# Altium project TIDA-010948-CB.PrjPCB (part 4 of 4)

## Sheet TIDA-010948-CB-Ethernet2.SchDoc
size 431 x 279 mm; Date: Not shown in title block; ApprovedBy: Not shown in title block; CheckedBy: Not shown in title block; Author: Not shown in title block; CompanyName: Not shown in title block; Engineer: Not shown in title block; Organization: Not shown in title block; Address1: Not shown in title block; Address2: Not shown in title block; Address3: Not shown in title block; Address4: Not shown in title block; DocumentNumber: 9; Revision: Use project parameter SCH_Rev; SheetNumber: 9; SheetTotal: 11; PageSetup: Record=PageOptions¦CenterHorizontal=True¦CenterVertical=True¦PrintScale=1.00¦XCorrection=1.00¦YCorrection=1.00¦PrintKind=0¦BorderSize=5000000¦LeftOffset=0¦BottomOffset=0¦Orientation=2¦PaperLength=1000¦PaperWidth=1000¦Scale=100¦PaperSource=15¦PrintQuality=600¦MediaType=1¦DitherType=10¦PaperKind=Letter¦PrintScaleMode=1
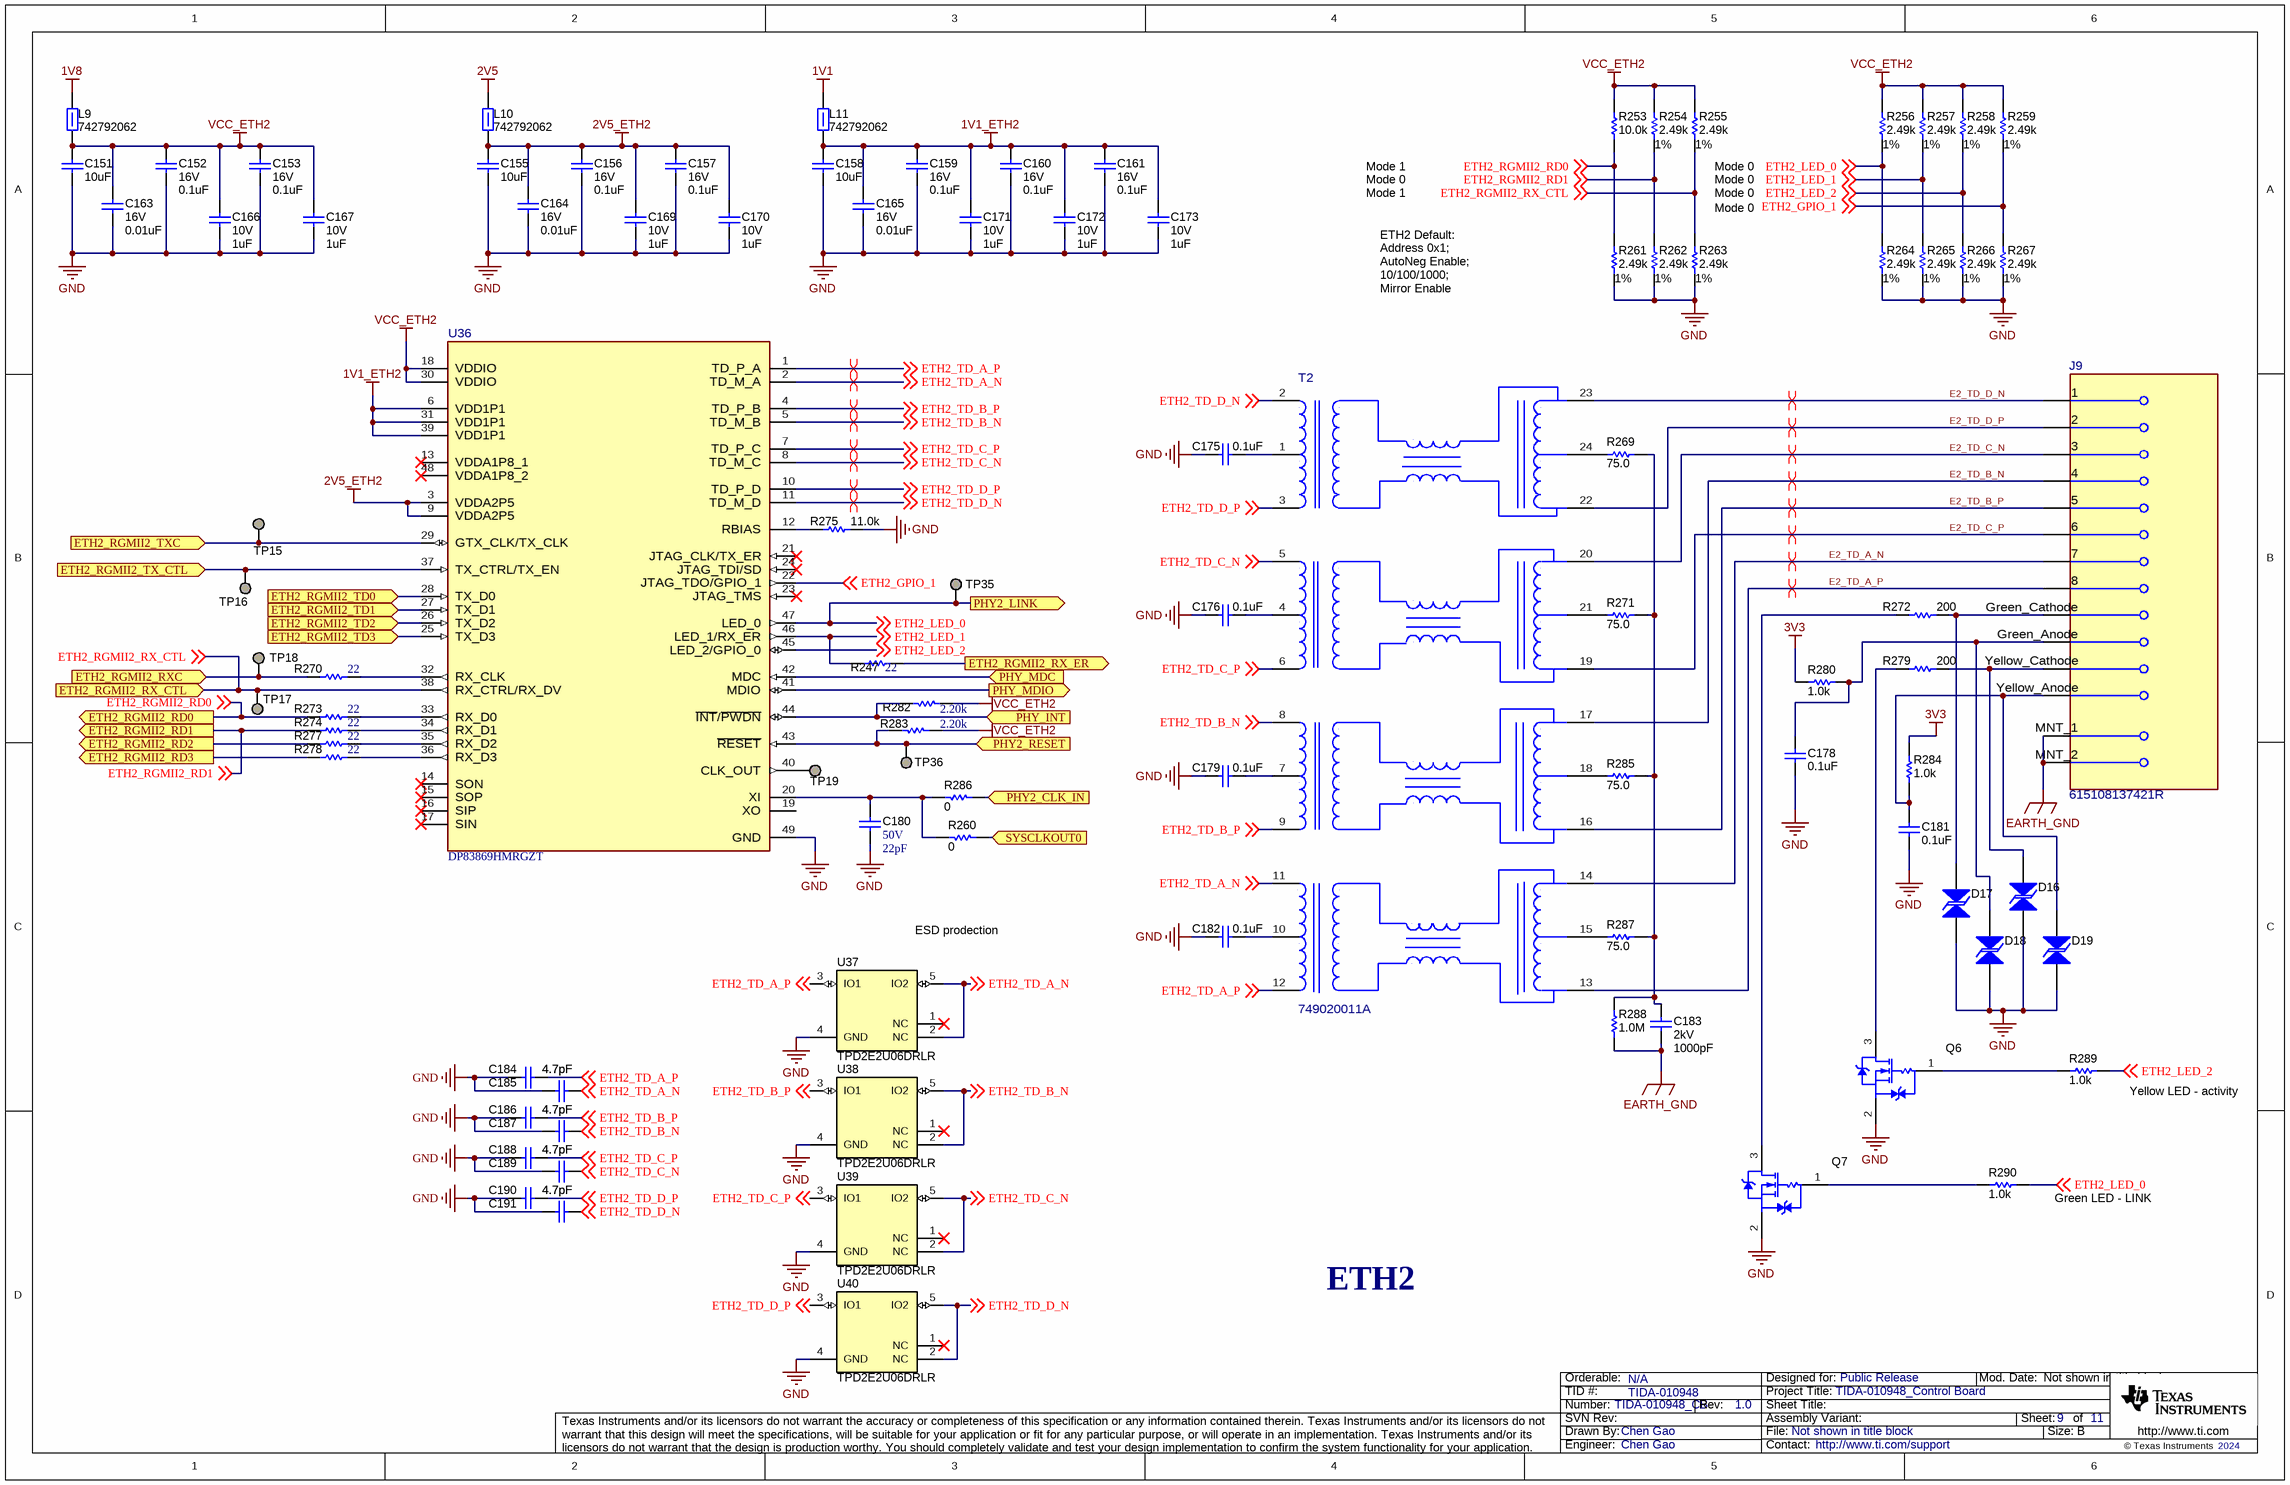
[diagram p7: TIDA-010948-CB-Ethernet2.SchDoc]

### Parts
C151  ValueDisplayed: 10uF  [1206_190]  (hidden comment: C3216X7R1V106M160AC)
C152  VDC_V: 16V  ValueDisplayed: 0.1uF  [0201_033]  (hidden comment: GRM033C71C104KE14D)
C153  VDC_V: 16V  ValueDisplayed: 0.1uF  [0201_033]  (hidden comment: GRM033C71C104KE14D)
C155  ValueDisplayed: 10uF  [1206_190]  (hidden comment: C3216X7R1V106M160AC)
C156  VDC_V: 16V  ValueDisplayed: 0.1uF  [0201_033]  (hidden comment: GRM033C71C104KE14D)
C157  VDC_V: 16V  ValueDisplayed: 0.1uF  [0201_033]  (hidden comment: GRM033C71C104KE14D)
C158  ValueDisplayed: 10uF  [1206_190]  (hidden comment: C3216X7R1V106M160AC)
C159  VDC_V: 16V  ValueDisplayed: 0.1uF  [0201_033]  (hidden comment: GRM033C71C104KE14D)
C160  VDC_V: 16V  ValueDisplayed: 0.1uF  [0201_033]  (hidden comment: GRM033C71C104KE14D)
C161  VDC_V: 16V  ValueDisplayed: 0.1uF  [0201_033]  (hidden comment: GRM033C71C104KE14D)
C163  VDC_V: 16V  ValueDisplayed: 0.01uF  [0402]  (hidden comment: 885012205031)
C164  VDC_V: 16V  ValueDisplayed: 0.01uF  [0402]  (hidden comment: 885012205031)
C165  VDC_V: 16V  ValueDisplayed: 0.01uF  [0402]  (hidden comment: 885012205031)
C166  VDC_V: 10V  ValueDisplayed: 1uF  [0201]  (hidden comment: GRM033R61A105ME15D)
C167  VDC_V: 10V  ValueDisplayed: 1uF  [0201]  (hidden comment: GRM033R61A105ME15D)
C169  VDC_V: 10V  ValueDisplayed: 1uF  [0201]  (hidden comment: GRM033R61A105ME15D)
C170  VDC_V: 10V  ValueDisplayed: 1uF  [0201]  (hidden comment: GRM033R61A105ME15D)
C171  VDC_V: 10V  ValueDisplayed: 1uF  [0201]  (hidden comment: GRM033R61A105ME15D)
C172  VDC_V: 10V  ValueDisplayed: 1uF  [0201]  (hidden comment: GRM033R61A105ME15D)
C173  VDC_V: 10V  ValueDisplayed: 1uF  [0201]  (hidden comment: GRM033R61A105ME15D)
C175  ValueDisplayed: 0.1uF  [0402]  (hidden comment: GRM155R71C104KA88D)
C176  ValueDisplayed: 0.1uF  [0402]  (hidden comment: GRM155R71C104KA88D)
C178  ValueDisplayed: 0.1uF  [0402]  (hidden comment: 885012105010)
C179  ValueDisplayed: 0.1uF  [0402]  (hidden comment: GRM155R71C104KA88D)
C180  VDC_V: 50V  ValueDisplayed: 22pF  [0402L]  (hidden comment: CGA2B2NP01H220J050BA)
C181  ValueDisplayed: 0.1uF  [0402]  (hidden comment: 885012105010)
C182  ValueDisplayed: 0.1uF  [0402]  (hidden comment: GRM155R71C104KA88D)
C183  VDC_V: 2kV  ValueDisplayed: 1000pF  [1808]  (hidden comment: GR442QR73D102KW01L)
C184  ValueDisplayed: 4.7pF  [0201L]  (hidden comment: GRM0335C1H4R7CA01D)
C185  ValueDisplayed: 4.7pF  [0201L]  (hidden comment: GRM0335C1H4R7CA01D)
C186  ValueDisplayed: 4.7pF  [0201L]  (hidden comment: GRM0335C1H4R7CA01D)
C187  ValueDisplayed: 4.7pF  [0201L]  (hidden comment: GRM0335C1H4R7CA01D)
C188  ValueDisplayed: 4.7pF  [0201L]  (hidden comment: GRM0335C1H4R7CA01D)
C189  ValueDisplayed: 4.7pF  [0201L]  (hidden comment: GRM0335C1H4R7CA01D)
C190  ValueDisplayed: 4.7pF  [0201L]  (hidden comment: GRM0335C1H4R7CA01D)
C191  ValueDisplayed: 4.7pF  [0201L]  (hidden comment: GRM0335C1H4R7CA01D)
D16  TPD1E1B04DPYR  [DPY0002A]  (value not drawn)
D17  TPD1E1B04DPYR  [DPY0002A]  (value not drawn)
D18  TPD1E1B04DPYR  [DPY0002A]  (value not drawn)
D19  TPD1E1B04DPYR  [DPY0002A]  (value not drawn)
J9  615108137421R  [FP-615108137421R_CONN_JACK_16MM4_15MM7-MFG]
L9  742792062  [0805_HV]
L10  742792062  [0805_HV]
L11  742792062  [0805_HV]
Q6  MOSFET_N_D3G1S2_PD2  [YJC0003A]  (value not drawn)
Q7  MOSFET_N_D3G1S2_PD2  [YJC0003A]  (value not drawn)
R247  ValueDisplayed: 22  [0402L]  (hidden comment: CRCW040222R0JNED)
R253  ValueDisplayed: 10.0k  [0402]  (hidden comment: CRCW040210K0FKED)
R254  Value1: 1%  ValueDisplayed: 2.49k  [0402]  (hidden comment: CRCW04022K49FKED)
R255  Value1: 1%  ValueDisplayed: 2.49k  [0402]  (hidden comment: CRCW04022K49FKED)
R256  Value1: 1%  ValueDisplayed: 2.49k  [0402]  (hidden comment: CRCW04022K49FKED)
R257  Value1: 1%  ValueDisplayed: 2.49k  [0402]  (hidden comment: CRCW04022K49FKED)
R258  Value1: 1%  ValueDisplayed: 2.49k  [0402]  (hidden comment: CRCW04022K49FKED)
R259  Value1: 1%  ValueDisplayed: 2.49k  [0402]  (hidden comment: CRCW04022K49FKED)
R260  ValueDisplayed: 0  [0402]  (hidden comment: CRCW04020000Z0ED)
R261  Value1: 1%  ValueDisplayed: 2.49k  [0402]  (hidden comment: CRCW04022K49FKED)
R262  Value1: 1%  ValueDisplayed: 2.49k  [0402]  (hidden comment: CRCW04022K49FKED)
R263  Value1: 1%  ValueDisplayed: 2.49k  [0402]  (hidden comment: CRCW04022K49FKED)
R264  Value1: 1%  ValueDisplayed: 2.49k  [0402]  (hidden comment: CRCW04022K49FKED)
R265  Value1: 1%  ValueDisplayed: 2.49k  [0402]  (hidden comment: CRCW04022K49FKED)
R266  Value1: 1%  ValueDisplayed: 2.49k  [0402]  (hidden comment: CRCW04022K49FKED)
R267  Value1: 1%  ValueDisplayed: 2.49k  [0402]  (hidden comment: CRCW04022K49FKED)
R269  ValueDisplayed: 75.0  [0805_HV]  (hidden comment: CRCW080575R0FKEA)
R270  ValueDisplayed: 22  [0402L]  (hidden comment: CRCW040222R0JNED)
R271  ValueDisplayed: 75.0  [0805_HV]  (hidden comment: CRCW080575R0FKEA)
R272  ValueDisplayed: 200  [0402]  (hidden comment: CRCW0402200RFKED)
R273  ValueDisplayed: 22  [0402L]  (hidden comment: CRCW040222R0JNED)
R274  ValueDisplayed: 22  [0402L]  (hidden comment: CRCW040222R0JNED)
R275  ValueDisplayed: 11.0k  [0402]  (hidden comment: CRCW040211K0FKED)
R277  ValueDisplayed: 22  [0402L]  (hidden comment: CRCW040222R0JNED)
R278  ValueDisplayed: 22  [0402L]  (hidden comment: CRCW040222R0JNED)
R279  ValueDisplayed: 200  [0402]  (hidden comment: CRCW0402200RFKED)
R280  ValueDisplayed: 1.0k  [0402]  (hidden comment: CRCW04021K00JNED)
R282  ValueDisplayed: 2.20k  [0402L]  (hidden comment: CRCW04022K20FKED)
R283  ValueDisplayed: 2.20k  [0402L]  (hidden comment: CRCW04022K20FKED)
R284  ValueDisplayed: 1.0k  [0402]  (hidden comment: CRCW04021K00JNED)
R285  ValueDisplayed: 75.0  [0805_HV]  (hidden comment: CRCW080575R0FKEA)
R286  ValueDisplayed: 0  [0402]  (hidden comment: CRCW04020000Z0ED)
R287  ValueDisplayed: 75.0  [0805_HV]  (hidden comment: CRCW080575R0FKEA)
R288  ValueDisplayed: 1.0M  [2010]  (hidden comment: CRCW20101M00JNEF)
R289  ValueDisplayed: 1.0k  [0402]  (hidden comment: CRCW04021K00JNED)
R290  ValueDisplayed: 1.0k  [0402]  (hidden comment: CRCW04021K00JNED)
T2  749020011A  [FP-749020011A_SMT_17MM5_14MM2-MFG]
TP15  TESTPOINT  [TP_25MIL-SMT]  (value not drawn)  (no BOM)
TP16  TESTPOINT  [TP_25MIL-SMT]  (value not drawn)  (no BOM)
TP17  TESTPOINT  [TP_25MIL-SMT]  (value not drawn)  (no BOM)
TP18  TESTPOINT  [TP_25MIL-SMT]  (value not drawn)  (no BOM)
TP19  TESTPOINT  [TP_25MIL-SMT]  (value not drawn)  (no BOM)
TP35  TESTPOINT  [TP_25MIL-SMT]  (value not drawn)  (no BOM)
TP36  TESTPOINT  [TP_25MIL-SMT]  (value not drawn)  (no BOM)
U36  DP83869HMRGZT  [RGZ0048B-MFG]
U37  TPD2E2U06DRLR  [DRL0005A]
U38  TPD2E2U06DRLR  [DRL0005A]
U39  TPD2E2U06DRLR  [DRL0005A]
U40  TPD2E2U06DRLR  [DRL0005A]

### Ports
ETH2_RGMII2_RD0 (out), ETH2_RGMII2_RD1 (out), ETH2_RGMII2_RD2 (out), ETH2_RGMII2_RD3 (out), ETH2_RGMII2_RX_CTL (in), ETH2_RGMII2_RX_ER (out), ETH2_RGMII2_RXC (in), ETH2_RGMII2_TD0 (in), ETH2_RGMII2_TD1 (in), ETH2_RGMII2_TD2 (in), ETH2_RGMII2_TD3 (in), ETH2_RGMII2_TX_CTL (in), ETH2_RGMII2_TXC (in), PHY2_CLK_IN (in), PHY2_LINK (out), PHY2_RESET (in), PHY_INT (in), PHY_MDC (in), PHY_MDIO (out), SYSCLKOUT0 (in)

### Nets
1V1: L11.2
1V1_ETH2: C158.1 C159.1 C160.1 C161.1 C165.1 C171.1 C172.1 C173.1 L11.1 U36.6(VDD1P1) U36.31(VDD1P1) U36.39(VDD1P1)
1V8: L9.2
2V5: L10.2
2V5_ETH2: C155.1 C156.1 C157.1 C164.1 C169.1 C170.1 L10.1 U36.3(VDDA2P5) U36.9(VDDA2P5)
3V3: R280.2 R284.1
EARTH_GND: C183.2 J9.13(MNT_1) J9.14(MNT_2) R288.1
GND: C151.2 C152.2 C153.2 C155.2 C156.2 C157.2 C158.2 C159.2 C160.2 C161.2 C163.2 C164.2 C165.2 C166.2 C167.2 C169.2 C170.2 C171.2 C172.2 C173.2 C175.2 C176.2 C178.1 C179.2 C180.2 C181.1 C182.2 C184.1 C185.1 C186.1 C187.1 C188.1 C189.1 C190.1 C191.1 D16.1 D17.1 D18.1 D19.1 Q6.2(S) Q7.2(S) R261.1 R262.1 R263.1 R264.1 R265.1 R266.1 R267.1 R275.2 U36.49(GND) U37.4(GND) U38.4(GND) U39.4(GND) U40.4(GND)
VCC_ETH2: C151.1 C152.1 C153.1 C163.1 C166.1 C167.1 L9.1 R253.2 R254.2 R255.2 R256.2 R257.2 R258.2 R259.2 R282.1 R283.1 U36.18(VDDIO) U36.30(VDDIO)
E2_TD_A_N: J9.7 T2.14(MX4+)
E2_TD_A_P: J9.8 T2.13(MX4-)
E2_TD_B_N: J9.4 T2.17(MX3+)
E2_TD_B_P: J9.5 T2.16(MX3-)
E2_TD_C_N: J9.3 T2.20(MX2+)
E2_TD_C_P: J9.6 T2.19(MX2-)
E2_TD_D_N: J9.1 T2.23(MX1+)
E2_TD_D_P: J9.2 T2.22(MX1-)
ETH2_GPIO_1: R259.1 R267.2 U36.22(JTAG_TDO/GPIO_1) ; off-sheet ETH2_GPIO_1
ETH2_LED_0: R256.1 R264.2 R290.1 TP35.1 U36.47(LED_0) ; off-sheet ETH2_LED_0, port PHY2_LINK
ETH2_LED_1: R247.1 R257.1 R265.2 U36.46(LED_1/RX_ER) ; off-sheet ETH2_LED_1
ETH2_LED_2: R258.1 R266.2 R289.1 U36.45(LED_2/GPIO_0) ; off-sheet ETH2_LED_2
ETH2_RGMII2_RD0: R253.1 R261.2 R273.1 ; off-sheet ETH2_RGMII2_RD0, port ETH2_RGMII2_RD0
ETH2_RGMII2_RD1: R254.1 R262.2 R274.1 ; off-sheet ETH2_RGMII2_RD1, port ETH2_RGMII2_RD1
ETH2_RGMII2_RD2: R277.1 ; port ETH2_RGMII2_RD2
ETH2_RGMII2_RD3: R278.1 ; port ETH2_RGMII2_RD3
ETH2_RGMII2_RX_CTL: R255.1 R263.2 TP17.1 U36.38(RX_CTRL/RX_DV) ; off-sheet ETH2_RGMII2_RX_CTL, port ETH2_RGMII2_RX_CTL
ETH2_RGMII2_RX_ER: R247.2 ; port ETH2_RGMII2_RX_ER
ETH2_RGMII2_RXC: R270.1 TP18.1 ; port ETH2_RGMII2_RXC
ETH2_RGMII2_TD0: U36.28(TX_D0) ; port ETH2_RGMII2_TD0
ETH2_RGMII2_TD1: U36.27(TX_D1) ; port ETH2_RGMII2_TD1
ETH2_RGMII2_TD2: U36.26(TX_D2) ; port ETH2_RGMII2_TD2
ETH2_RGMII2_TD3: U36.25(TX_D3) ; port ETH2_RGMII2_TD3
ETH2_RGMII2_TX_CTL: TP16.1 U36.37(TX_CTRL/TX_EN) ; port ETH2_RGMII2_TX_CTL
ETH2_RGMII2_TXC: TP15.1 U36.29(GTX_CLK/TX_CLK) ; port ETH2_RGMII2_TXC
ETH2_TD_A_N: C185.2 T2.11(TD4+) U36.2(TD_M_A) U37.2(NC) U37.5(IO2) ; off-sheet ETH2_TD_A_N
ETH2_TD_A_P: C184.2 T2.12(TD4-) U36.1(TD_P_A) U37.3(IO1) ; off-sheet ETH2_TD_A_P
ETH2_TD_B_N: C187.2 T2.8(TD3+) U36.5(TD_M_B) U38.2(NC) U38.5(IO2) ; off-sheet ETH2_TD_B_N
ETH2_TD_B_P: C186.2 T2.9(TD3-) U36.4(TD_P_B) U38.3(IO1) ; off-sheet ETH2_TD_B_P
ETH2_TD_C_N: C189.2 T2.5(TD2+) U36.8(TD_M_C) U39.2(NC) U39.5(IO2) ; off-sheet ETH2_TD_C_N
ETH2_TD_C_P: C188.2 T2.6(TD2-) U36.7(TD_P_C) U39.3(IO1) ; off-sheet ETH2_TD_C_P
ETH2_TD_D_N: C191.2 T2.2(TD1+) U36.11(TD_M_D) U40.2(NC) U40.5(IO2) ; off-sheet ETH2_TD_D_N
ETH2_TD_D_P: C190.2 T2.3(TD1-) U36.10(TD_P_D) U40.3(IO1) ; off-sheet ETH2_TD_D_P
PHY2_CLK_IN: R286.1 ; port PHY2_CLK_IN
PHY2_RESET: R283.2 TP36.1 U36.43(~{RESET}) ; port PHY2_RESET
PHY_INT: R282.2 U36.44(~{INT}/~{PWDN}) ; port PHY_INT
PHY_MDC: U36.42(MDC) ; port PHY_MDC
PHY_MDIO: U36.41(MDIO) ; port PHY_MDIO
SYSCLKOUT0: R260.1 ; port SYSCLKOUT0
NetC175_1: C175.1 T2.1(TCT1)
NetC176_1: C176.1 T2.4(TCT2)
NetC178_2: C178.2 D18.2 J9.10(Green_Anode) R280.1
NetC179_1: C179.1 T2.7(TCT3)
NetC180_1: C180.1 R260.2 R286.2 U36.20(XI)
NetC181_2: C181.2 D19.2 J9.12(Yellow_Anode) R284.2
NetC182_1: C182.1 T2.10(TCT4)
NetC183_1: C183.1 R269.2 R271.2 R285.2 R287.2 R288.2
NetD16_2: D16.2 J9.11(Yellow_Cathode) R279.2
NetD17_2: D17.2 J9.9(Green_Cathode) R272.2
NetQ6_1: Q6.1(G) R289.2
NetQ6_3: Q6.3(D) R279.1
NetQ7_1: Q7.1(G) R290.2
NetQ7_3: Q7.3(D) R272.1
NetR269_1: R269.1 T2.24(MCT1)
NetR270_2: R270.2 U36.32(RX_CLK)
NetR271_1: R271.1 T2.21(MCT2)
NetR273_2: R273.2 U36.33(RX_D0)
NetR274_2: R274.2 U36.34(RX_D1)
NetR275_1: R275.1 U36.12(RBIAS)
NetR277_2: R277.2 U36.35(RX_D2)
NetR278_2: R278.2 U36.36(RX_D3)
NetR285_1: R285.1 T2.18(MCT3)
NetR287_1: R287.1 T2.15(MCT4)
NetTP19_1: TP19.1 U36.40(CLK_OUT)

Not connected (* = marked no-connect by the designer): U36 13(VDDA1P8_1)* 14(SON)* 15(SOP)* 16(SIP)* 17(SIN)* 19(XO) 21(JTAG_CLK/TX_ER)* 23(JTAG_TMS)* 24(JTAG_TDI/SD)* 48(VDDA1P8_2)*; U37 1(NC)*; U38 1(NC)*; U39 1(NC)*; U40 1(NC)*

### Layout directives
differential pair: E2_TD_A_N, E2_TD_A_P, E2_TD_B_N, E2_TD_B_P, E2_TD_C_N, E2_TD_C_P, E2_TD_D_N, E2_TD_D_P, ETH2_TD_A_N, ETH2_TD_A_P, ETH2_TD_B_N, ETH2_TD_B_P, ETH2_TD_C_N, ETH2_TD_C_P, ETH2_TD_D_N, ETH2_TD_D_P

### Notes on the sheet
- Mode 1
- (near R255) Mode 0
- Mode 0
- (near R263) Mode 0
- ETH2 Default:
  Address 0x1;
  AutoNeg Enable;
  10/100/1000;
  Mirror Enable
- (near U37) ESD prodection
- (near R289) Yellow LED - activity
- (near R290) Green LED - LINK
- ETH2

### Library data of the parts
C151 C155 C158 = CMP-0008706-2: CAP, CERM, 10 uF, 35 V, +/- 20%, X7R, 1206_190; Manufacturer: TDK; Polarized: N; Value: 10uF; U/M: EA; Cap_F: 10µF; Value1: Unknown; VDC_V: 35V; TaMin_C: -55°C; TaMax_C: 125°C; Cap_Case: 1206; AEC Category: Q200; SizeArea_mm2: 5.12; SizeAreaWB_mm2: 10.92; SizeX_mm: 3.2; SizeY_mm: 1.6; SizeZ_mm: 1.9
C152 C153 C156 C157 C159-C161 = CMP-0009670-3: CAP, CERM, 0.1 uF, 16 V, +/- 10%, X5R, 0201; Manufacturer: MuRata; TaMin_C: -55°C; Polarized: N; SizeAreaWB_mm2: 2.08; Value1: Unknown; U/M: EA; Value: 0.1uF; TaMax_C: 125°C; SizeZ_mm: 0.33; SizeX_mm: 0.6; SizeY_mm: 0.3; Cap_Case: 0201; SizeArea_mm2: 0.18; Cap_F: 100nF; AEC Category: Q200
C163-C165 = CMP-0006227-2: CAP, CERM, 0.01 uF, 16 V, +/- 10%, X7R, 0402; Manufacturer: Wurth Elektronik; TaMin_C: -55°C; Polarized: N; SizeAreaWB_mm2: 3; Value1: Unknown; U/M: EA; Value: 0.01uF; TaMax_C: 125°C; SizeZ_mm: 0.6; SizeX_mm: 1; SizeY_mm: 0.5; Cap_F: 10nF; AEC Category: Q200
C166 C167 C169-C173 = CMP-0064909-1: CAP, CERM, 1 uF, 10 V,+/- 20%, X5R, 0201; Manufacturer: MuRata; TaMin_C: -55°C; Polarized: N; SizeAreaWB_mm2: 2.08; Value1: Unknown; U/M: EA; Value: 1uF; TaMax_C: 85°C; SizeZ_mm: 0.26; SizeX_mm: 0.6; SizeY_mm: 0.3; SizeArea_mm2: 0.18; Cap_F: 1µF; AEC Category: Q200
C175 C176 C179 C182 = CMP-0006641-2: CAP, CERM, 0.1 uF, 16 V, +/- 10%, X7R, 0402; Manufacturer: MuRata; TaMin_C: -55°C; Polarized: N; SizeAreaWB_mm2: 3; Value1: Unknown; U/M: EA; Value: 0.1uF; TaMax_C: 125°C; SizeZ_mm: 0.6; SizeX_mm: 1; SizeY_mm: 0.5; Value2: 16V; Cap_F: 100nF; AEC Category: Q200
C178 C181 = CMP-0006221-2: CAP, CERM, 0.1 uF, 10 V, +/- 20%, X5R, 0402; Manufacturer: Wurth Elektronik; TaMin_C: -55°C; Polarized: N; SizeAreaWB_mm2: 3; Value1: Unknown; U/M: EA; Value: 0.1uF; TaMax_C: 85°C; SizeZ_mm: 0.6; SizeX_mm: 1; SizeY_mm: 0.5; Value2: 10V; Cap_F: 100nF; AEC Category: Q200
C180 = CMP-0006311-2: CAP, CERM, 22 pF, 50 V, +/- 5%, C0G/NP0, AEC-Q200 Grade 1, 0402; Manufacturer: TDK; TaMin_C: -55°C; Polarized: N; SizeAreaWB_mm2: 3; Value1: Unknown; U/M: EA; Value: 22pF; TaMax_C: 125°C; SizeZ_mm: 0.6; SizeX_mm: 1; SizeY_mm: 0.5; Cap_Case: 0402; AEC Qualified: Y; AEC Category: Q200
C183 = CMP-0009436-2: CAP, CERM, 1000 pF, 2000 V, +/- 10%, X7R, 1808; Manufacturer: MuRata; TaMin_C: -55°C; Polarized: N; SizeAreaWB_mm2: 16.5; Value1: Unknown; U/M: EA; Value: 1000pF; TaMax_C: 125°C; SizeZ_mm: 2.03; SizeX_mm: 4.5; SizeY_mm: 2; Value2: 2000V; SizeArea_mm2: 9; Cap_F: 1nF; AEC Category: Q200
C184-C191 = CMP-0009667-3: CAP, CERM, 4.7 pF, 50 V, +/- 5%, C0G/NP0, 0201; Manufacturer: MuRata; Polarized: N; Value: 4.7pF; U/M: EA; Value1: Unknown; VDC_V: 50V; TaMin_C: -55°C; TaMax_C: 125°C; Cap_Case: 0201; AEC Category: Q200; SizeArea_mm2: 0.18; SizeAreaWB_mm2: 2.08; SizeX_mm: 0.6; SizeY_mm: 0.3; SizeZ_mm: 0.26
D16-D19 = CMP-0073609-3: 1-Channel ESD Protection Diode With Low Dynamic Resistance and Low Clamping Voltage, DPY0002A (X1SON-2); PartNumber: TPD1E1B04DPYT; Manufacturer: Texas Instruments; SizeX_mm: 1.0; Rating: Catalog; SizeY_mm: 0.6; SizeAreaWB_mm2: 3.2; SizeZ_mm: 0.45; AEC Category: Q200; CompType: IC
J9 = CMP-0087236-1: WR-MJ Modular Jack THR Horizontal Shielded w. LED and EMI Finger 8P8C Tab Up; Manufacturer: Wurth Electronics Inc.; Current_A: 1.5A; ContactFinish: Gold; Shrouded: true; Voltage_V: 125V
L9-L11 = CMP-0003092-1: Ferrite Bead, 80 ohm @ 100 MHz, 0.5 A, 0805; Manufacturer: Wurth Elektronik; Ztyp@1GHz_Ohm: 146.576; ZTyp@100MHz_Ohm: 80; SizeAreaWB_mm2: 6.75; DCR_ohm: 0.2; Value1: 0.2 ohm; Value: 80 ohm; Imax_A: 500mA; SizeZ_mm: 1.45; SizeX_mm: 2; SizeY_mm: 1.25; Value2: 0.5A; SizeArea_mm2: 2.5
Q6 Q7 = CMP-0000198-1: MOSFET, N-CH, 12 V, 2.9 A, YJC0003A (PICOSTAR-3); PartNumber: CSD13383F4; Manufacturer: Texas Instruments; Alternate Manufacturer: None; U/M: EA; ChType: N; Value: 12V; Value1: 0.04; Rdson45_ohm: 0.044; Value2: 2 nC; QgTyp_nC: 2; Vgs_V: 10V; IdsMax_A: 2.9A; AEC Category: Q101; SizeArea_mm2: 0.657225; SizeAreaWB_mm2: 3.327225; SizeX_mm: 1.035; SizeY_mm: 0.635; SizeZ_mm: 0.35
R247 R270 R273 R274 R277 R278 = CMP-0026880-3: RES, 22, 5%, 0.063 W, AEC-Q200 Grade 0, 0402; Manufacturer: Vishay-Dale; Power_W: 63mW; TempCo: 200 ppm/C; Value_Code: 22R0; Value: 22; EIA_Code: E24; SizeX_mm: 1; SizeY_mm: 0.5; SizeZ_mm: 0.6; Value2: 0.063W; AEC Qualified: Y; VDC_V: 50V; AEC Category: Q200; AEC Grade: 0
R253 = CMP-0025958-3: RES, 10.0 k, 1%, 0.063 W, AEC-Q200 Grade 0, 0402; Manufacturer: Vishay-Dale; Power_W: 63mW; TempCo: 100 ppm/C; Value_Code: 10k0; Value: 10.0k; EIA_Code: E96; Res_ohm: 10k; SizeX_mm: 1; SizeY_mm: 0.5; SizeZ_mm: 0.6; Value2: 0.063W; AEC Qualified: Y; VDC_V: 50V; AEC Category: Q200; AEC Grade: 0
R254-R259 R261-R267 = CMP-0026237-2: RES, 2.49 k, 1%, 0.063 W, AEC-Q200 Grade 0, 0402; Manufacturer: Vishay-Dale; Power_W: 63mW; TempCo: 100 ppm/C; Value_Code: 2k49; Value: 2.49k; EIA_Code: E96; SizeX_mm: 1; SizeY_mm: 0.5; SizeZ_mm: 0.6; Value2: 0.063W; AEC Qualified: Y; VDC_V: 50V; AEC Grade: 0; AEC Category: Q200
R260 R286 = CMP-0026822-3: RES, 0, 5%, 0.063 W, AEC-Q200 Grade 0, 0402; Manufacturer: Vishay-Dale; Power_W: 63mW; TempCo: 200 ppm/C; Value_Code: 0000; Value: 0; EIA_Code: E24; SizeX_mm: 1; SizeY_mm: 0.5; SizeZ_mm: 0.6; Value2: 0.063W; AEC Qualified: Y; VDC_V: 50V; AEC Category: Q200
R269 R271 R285 R287 = CMP-0021425-3: RES, 75.0, 1%, 0.125 W, AEC-Q200 Grade 0, 0805; Manufacturer: Vishay-Dale; Power_W: 125mW; TempCo: 100 ppm/C; Value_Code: 75R0; Value: 75.0; EIA_Code: E96; Res_ohm: 75; SizeX_mm: 2; SizeY_mm: 1.25; SizeZ_mm: 1.45; Value2: 0.125W; SizeArea_mm2: 2.5; AEC Qualified: Y; VDC_V: 150V; AEC Category: Q200; AEC Grade: 0
R272 R279 = CMP-0026159-2: RES, 200, 1%, 0.063 W, AEC-Q200 Grade 0, 0402; Manufacturer: Vishay-Dale; Power_W: 63mW; TempCo: 100 ppm/C; Value_Code: 200R; Value: 200; EIA_Code: E96; SizeX_mm: 1; SizeY_mm: 0.5; SizeZ_mm: 0.6; Value2: 0.063W; AEC Qualified: Y; VDC_V: 50V; AEC Category: Q200; AEC Grade: 0
R275 = CMP-0025975-3: RES, 11.0 k, 1%, 0.063 W, AEC-Q200 Grade 0, 0402; Manufacturer: Vishay-Dale; Power_W: 63mW; TempCo: 100 ppm/C; Value_Code: 11k0; Value: 11.0k; EIA_Code: E96; Res_ohm: 11k; SizeX_mm: 1; SizeY_mm: 0.5; SizeZ_mm: 0.6; Value2: 0.063W; AEC Qualified: Y; VDC_V: 50V; AEC Category: Q200; AEC Grade: 0
R280 R284 R289 R290 = CMP-0026852-1: RES, 1.0 k, 5%, 0.063 W, 0402; Manufacturer: Vishay-Dale; Power_W: 63mW; TempCo: 200 ppm/C; Value_Code: 1k00; U/M: EA; Value: 1.0k; EIA_Code: E24; Res_ohm: 1k; SizeX_mm: 1; SizeY_mm: 0.5; SizeZ_mm: 0.6; Value2: 0.063W; VDC_V: 50V; AEC Category: Q200
R282 R283 = CMP-0026231-2: RES, 2.20 k, 1%, 0.063 W, AEC-Q200 Grade 0, 0402; Manufacturer: Vishay-Dale; Power_W: 63mW; TempCo: 100 ppm/C; Value_Code: 2k20; Value: 2.20k; Res_ohm: 2.2k; SizeX_mm: 1; SizeY_mm: 0.5; SizeZ_mm: 0.6; Value2: 0.063W; AEC Qualified: Y; AEC Category: Q200; AEC Grade: 0
R288 = CMP-0016081-3: RES, 1.0 M, 5%, 0.75 W, AEC-Q200 Grade 0, 2010; Manufacturer: Vishay-Dale; Power_W: 750mW; TempCo: 200 ppm/C; Value_Code: 1M00; Value: 1.0Meg; EIA_Code: E24; Res_ohm: 1M; SizeX_mm: 5; SizeY_mm: 2.5; SizeZ_mm: 1.66; Value2: 0.75W; SizeArea_mm2: 12.5; AEC Qualified: Y; VDC_V: 400V; AEC Grade: 0; AEC Category: Q200
T2 = CMP-0086582-1: WURTH ELEKTRONIK LAN TRANSFORMER, 10/100/1000 BASE-T; Manufacturer: Wurth Electronics; Ind_H: 350µH; SizeZ_mm: 6.5mm; AEC Qualified: No; Ns1toNp: 1:1
TP15-TP19 TP35 TP36 = CMP-0078143-3: TEST POINT.  No entry in BOM.
U36 = CMP-0091377-1: 1/1 Transceiver Ethernet 48-VQFN (7x7); Manufacturer: Texas Instruments; TaMin_C: -40°C; SizeZ_mm: 1mm; TaMax_C: +125°C; Max Supply Voltage: 3.45V; Number Of Channels: 1; AEC Qualified: No; Data Rate: 1000Mbits/s; Min Supply Voltage: 990mV; Simplex Duplex: Full-Duplex; Standoff Height: 0mm
U37-U40 = CMP-0066602-2: Dual-Channel High-Speed ESD Protection, DRL0005A (SOT-OTHER-5); Alternate Manufacturer: Texas Instruments; Green_Lifecycle: Active; SizeAreaWB_mm2: 6.76; Green_REACh: Passed; U/M: EA; SizeZ_mm: 0.6; SizeX_mm: 1.6; SizeArea_mm2: 2.56; CompType: IC

## Sheet TIDA-010948-CB-Interface.SchDoc
size 431 x 279 mm; Date: Not shown in title block; ApprovedBy: Not shown in title block; CheckedBy: Not shown in title block; Author: Not shown in title block; CompanyName: Not shown in title block; Engineer: Not shown in title block; Organization: Not shown in title block; Address1: Not shown in title block; Address2: Not shown in title block; Address3: Not shown in title block; Address4: Not shown in title block; DocumentNumber: 10; Revision: Use project parameter SCH_Rev; SheetNumber: 10; SheetTotal: 11; PageSetup: Record=PageOptions¦CenterHorizontal=True¦CenterVertical=True¦PrintScale=1.00¦XCorrection=1.00¦YCorrection=1.00¦PrintKind=0¦BorderSize=5000000¦LeftOffset=0¦BottomOffset=0¦Orientation=2¦PaperLength=1000¦PaperWidth=1000¦Scale=100¦PaperSource=15¦PrintQuality=600¦MediaType=1¦DitherType=10¦PaperKind=Letter¦PrintScaleMode=1
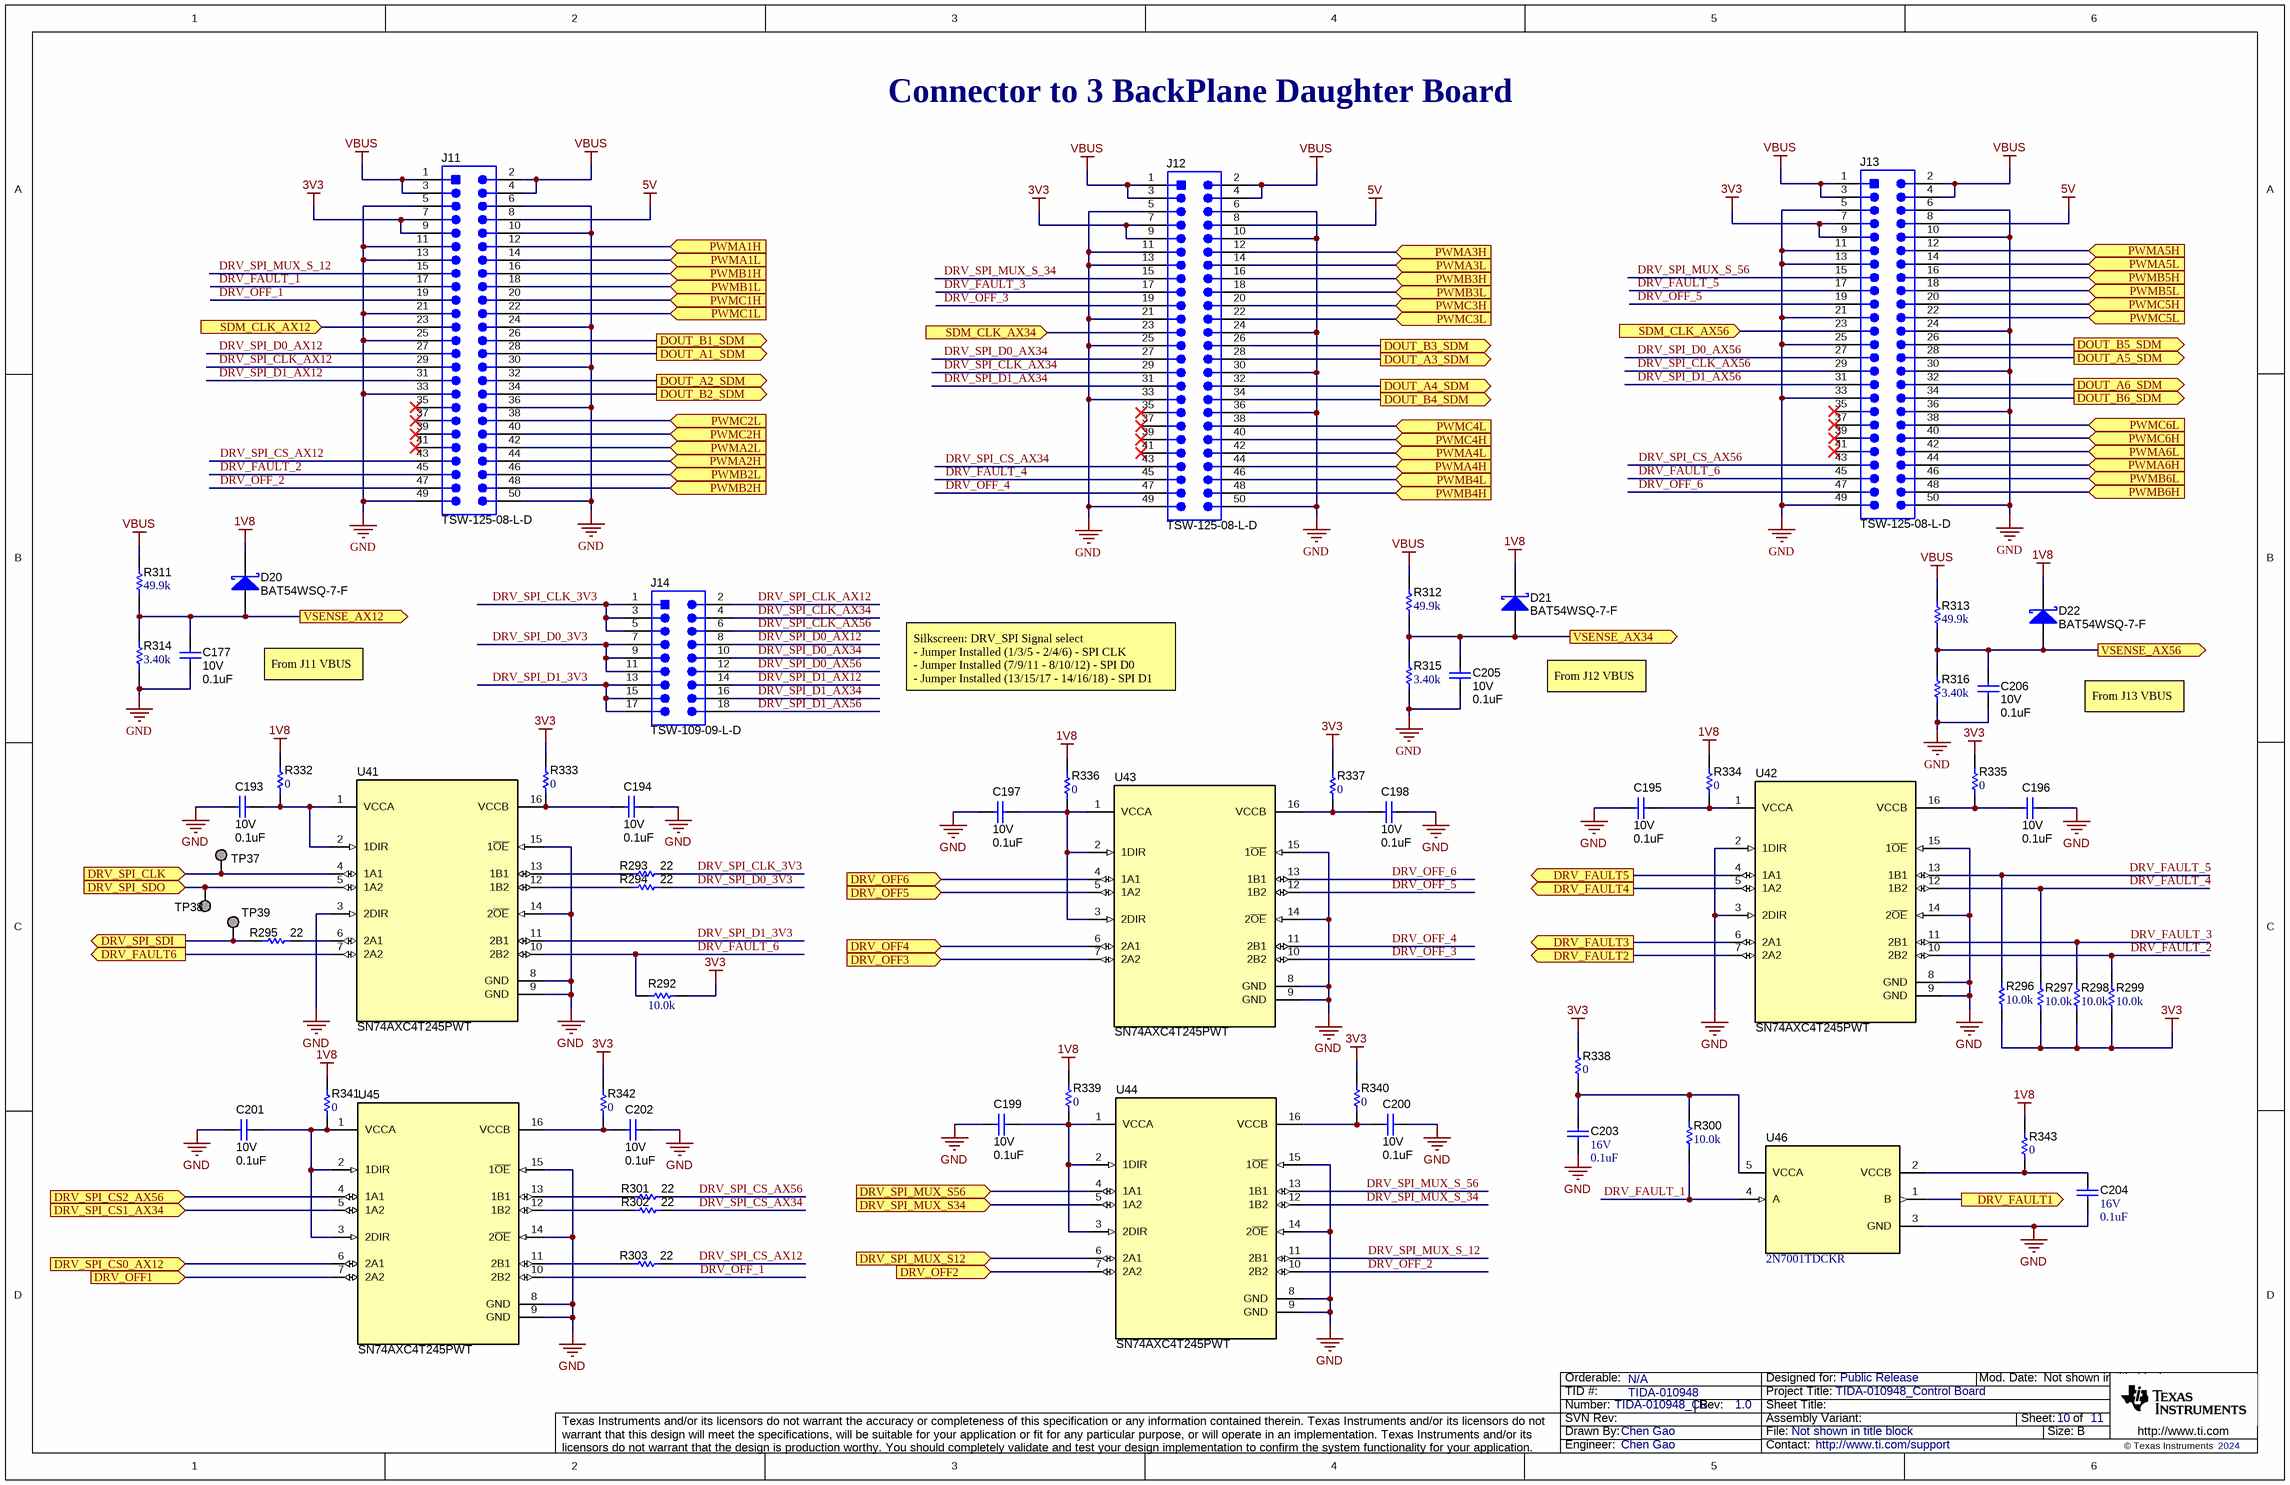
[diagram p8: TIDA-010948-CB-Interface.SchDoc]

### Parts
C177  VDC_V: 10V  ValueDisplayed: 0.1uF  [0402]  (hidden comment: GRM155R71A104KA01D)
C193  VDC_V: 10V  ValueDisplayed: 0.1uF  [0402]  (hidden comment: GRM155R71A104KA01D)
C194  VDC_V: 10V  ValueDisplayed: 0.1uF  [0402]  (hidden comment: GRM155R71A104KA01D)
C195  VDC_V: 10V  ValueDisplayed: 0.1uF  [0402]  (hidden comment: GRM155R71A104KA01D)
C196  VDC_V: 10V  ValueDisplayed: 0.1uF  [0402]  (hidden comment: GRM155R71A104KA01D)
C197  VDC_V: 10V  ValueDisplayed: 0.1uF  [0402]  (hidden comment: GRM155R71A104KA01D)
C198  VDC_V: 10V  ValueDisplayed: 0.1uF  [0402]  (hidden comment: GRM155R71A104KA01D)
C199  VDC_V: 10V  ValueDisplayed: 0.1uF  [0402]  (hidden comment: GRM155R71A104KA01D)
C200  VDC_V: 10V  ValueDisplayed: 0.1uF  [0402]  (hidden comment: GRM155R71A104KA01D)
C201  VDC_V: 10V  ValueDisplayed: 0.1uF  [0402]  (hidden comment: GRM155R71A104KA01D)
C202  VDC_V: 10V  ValueDisplayed: 0.1uF  [0402]  (hidden comment: GRM155R71A104KA01D)
C203  VDC_V: 16V  ValueDisplayed: 0.1uF  [0201]  (hidden comment: GRM033Z71C104KE14D)
C204  VDC_V: 16V  ValueDisplayed: 0.1uF  [0201]  (hidden comment: GRM033Z71C104KE14D)
C205  VDC_V: 10V  ValueDisplayed: 0.1uF  [0402]  (hidden comment: GRM155R71A104KA01D)
C206  VDC_V: 10V  ValueDisplayed: 0.1uF  [0402]  (hidden comment: GRM155R71A104KA01D)
D20  BAT54WSQ-7-F  [SOD-323]
D21  BAT54WSQ-7-F  [SOD-323]
D22  BAT54WSQ-7-F  [SOD-323]
J11  TSW-125-08-L-D  [Samtec_TSW-125-08-x-D]
J12  TSW-125-08-L-D  [Samtec_TSW-125-08-x-D]
J13  TSW-125-08-L-D  [Samtec_TSW-125-08-x-D]
J14  TSW-109-09-L-D  [Samtec_TSW-109-09-x-D]
R292  ValueDisplayed: 10.0k  [0402L]  (hidden comment: CRCW040210K0FKED)
R293  ValueDisplayed: 22  [0402]  (hidden comment: CRCW040222R0JNED)
R294  ValueDisplayed: 22  [0402]  (hidden comment: CRCW040222R0JNED)
R295  ValueDisplayed: 22  [0402]  (hidden comment: CRCW040222R0JNED)
R296  ValueDisplayed: 10.0k  [0402L]  (hidden comment: CRCW040210K0FKED)
R297  ValueDisplayed: 10.0k  [0402L]  (hidden comment: CRCW040210K0FKED)
R298  ValueDisplayed: 10.0k  [0402L]  (hidden comment: CRCW040210K0FKED)
R299  ValueDisplayed: 10.0k  [0402L]  (hidden comment: CRCW040210K0FKED)
R300  ValueDisplayed: 10.0k  [0402L]  (hidden comment: CRCW040210K0FKED)
R301  ValueDisplayed: 22  [0402]  (hidden comment: CRCW040222R0JNED)
R302  ValueDisplayed: 22  [0402]  (hidden comment: CRCW040222R0JNED)
R303  ValueDisplayed: 22  [0402]  (hidden comment: CRCW040222R0JNED)
R311  ValueDisplayed: 49.9k  [0603]  (hidden comment: RT0603DRE0749K9L)
R312  ValueDisplayed: 49.9k  [0603]  (hidden comment: RT0603DRE0749K9L)
R313  ValueDisplayed: 49.9k  [0603]  (hidden comment: RT0603DRE0749K9L)
R314  ValueDisplayed: 3.40k  [0603]  (hidden comment: RT0603DRE073K4L)
R315  ValueDisplayed: 3.40k  [0603]  (hidden comment: RT0603DRE073K4L)
R316  ValueDisplayed: 3.40k  [0603]  (hidden comment: RT0603DRE073K4L)
R332  ValueDisplayed: 0  [0402L]  (hidden comment: ERJ-2GE0R00X)
R333  ValueDisplayed: 0  [0402L]  (hidden comment: ERJ-2GE0R00X)
R334  ValueDisplayed: 0  [0402L]  (hidden comment: ERJ-2GE0R00X)
R335  ValueDisplayed: 0  [0402L]  (hidden comment: ERJ-2GE0R00X)
R336  ValueDisplayed: 0  [0402L]  (hidden comment: ERJ-2GE0R00X)
R337  ValueDisplayed: 0  [0402L]  (hidden comment: ERJ-2GE0R00X)
R338  ValueDisplayed: 0  [0402L]  (hidden comment: ERJ-2GE0R00X)
R339  ValueDisplayed: 0  [0402L]  (hidden comment: ERJ-2GE0R00X)
R340  ValueDisplayed: 0  [0402L]  (hidden comment: ERJ-2GE0R00X)
R341  ValueDisplayed: 0  [0402L]  (hidden comment: ERJ-2GE0R00X)
R342  ValueDisplayed: 0  [0402L]  (hidden comment: ERJ-2GE0R00X)
R343  ValueDisplayed: 0  [0402L]  (hidden comment: ERJ-2GE0R00X)
TP37  TESTPOINT  [TP_25MIL-SMT]  (value not drawn)  (no BOM)
TP38  TESTPOINT  [TP_25MIL-SMT]  (value not drawn)  (no BOM)
TP39  TESTPOINT  [TP_25MIL-SMT]  (value not drawn)  (no BOM)
U41  SN74AXC4T245PWT  [PW0016A_N]
U42  SN74AXC4T245PWT  [PW0016A_N]
U43  SN74AXC4T245PWT  [PW0016A_N]
U44  SN74AXC4T245PWT  [PW0016A_N]
U45  SN74AXC4T245PWT  [PW0016A_N]
U46  2N7001TDCKR  [DCK0005A_N]

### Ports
DOUT_A1_SDM (out), DOUT_A2_SDM (out), DOUT_A3_SDM (out), DOUT_A4_SDM (out), DOUT_A5_SDM (out), DOUT_A6_SDM (out), DOUT_B1_SDM (out), DOUT_B2_SDM (out), DOUT_B3_SDM (out), DOUT_B4_SDM (out), DOUT_B5_SDM (out), DOUT_B6_SDM (out), DRV_FAULT1 (out), DRV_FAULT2 (out), DRV_FAULT3 (out), DRV_FAULT4 (out), DRV_FAULT5 (out), DRV_FAULT6 (out), DRV_OFF1 (in), DRV_OFF2 (in), DRV_OFF3 (in), DRV_OFF4 (in), DRV_OFF5 (in), DRV_OFF6 (in), DRV_SPI_CLK (in), DRV_SPI_CS0_AX12 (in), DRV_SPI_CS1_AX34 (in), DRV_SPI_CS2_AX56 (in), DRV_SPI_MUX_S12 (in), DRV_SPI_MUX_S34 (in), DRV_SPI_MUX_S56 (in), DRV_SPI_SDI (out), DRV_SPI_SDO (in), PWMA1H (in), PWMA1L (in), PWMA2H (in), PWMA2L (in), PWMA3H (in), PWMA3L (in), PWMA4H (in), PWMA4L (in), PWMA5H (in), PWMA5L (in), PWMA6H (in), PWMA6L (in), PWMB1H (in), PWMB1L (in), PWMB2H (in), PWMB2L (in), PWMB3H (in), PWMB3L (in), PWMB4H (in), PWMB4L (in), PWMB5H (in), PWMB5L (in), PWMB6H (in), PWMB6L (in), PWMC1H (in), PWMC1L (in), PWMC2H (in), PWMC2L (in), PWMC3H (in), PWMC3L (in), PWMC4H (in), PWMC4L (in), PWMC5H (in), PWMC5L (in), PWMC6H (in), PWMC6L (in), SDM_CLK_AX12 (in), SDM_CLK_AX34 (in), SDM_CLK_AX56 (in), VSENSE_AX12 (out), VSENSE_AX34 (out), VSENSE_AX56 (out)

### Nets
1V8: D20.1(K) D21.1(K) D22.1(K) R332.2 R334.2 R336.2 R339.2 R341.2 R343.2
3V3: J11.7 J11.9 J12.7 J12.9 J13.7 J13.9 R292.1 R296.1 R297.1 R298.1 R299.1 R333.2 R335.2 R337.2 R338.2 R340.2 R342.2
5V: J11.8 J12.8 J13.8
GND: C177.1 C193.1 C194.2 C195.1 C196.2 C197.1 C198.2 C199.1 C200.2 C201.1 C202.2 C203.2 C204.2 C205.1 C206.1 J11.5 J11.6 J11.10 J11.11 J11.13 J11.21 J11.24 J11.25 J11.30 J11.33 J11.36 J11.49 J11.50 J12.5 J12.6 J12.10 J12.11 J12.13 J12.21 J12.24 J12.25 J12.30 J12.33 J12.36 J12.49 J12.50 J13.5 J13.6 J13.10 J13.11 J13.13 J13.21 J13.24 J13.25 J13.30 J13.33 J13.36 J13.49 J13.50 R314.1 R315.1 R316.1 U41.3(2DIR) U41.8(GND) U41.9(GND) U41.14(2~{OE}) U41.15(1~{OE}) U42.2(1DIR) U42.3(2DIR) U42.8(GND) U42.9(GND) U42.14(2~{OE}) U42.15(1~{OE}) U43.8(GND) U43.9(GND) U43.14(2~{OE}) U43.15(1~{OE}) U44.8(GND) U44.9(GND) U44.14(2~{OE}) U44.15(1~{OE}) U45.8(GND) U45.9(GND) U45.14(2~{OE}) U45.15(1~{OE}) U46.3(GND)
VBUS: J11.1 J11.2 J11.3 J11.4 J12.1 J12.2 J12.3 J12.4 J13.1 J13.2 J13.3 J13.4 R311.2 R312.2 R313.2
DOUT_A1_SDM: J11.28 ; port DOUT_A1_SDM
DOUT_A2_SDM: J11.32 ; port DOUT_A2_SDM
DOUT_A3_SDM: J12.28 ; port DOUT_A3_SDM
DOUT_A4_SDM: J12.32 ; port DOUT_A4_SDM
DOUT_A5_SDM: J13.28 ; port DOUT_A5_SDM
DOUT_A6_SDM: J13.32 ; port DOUT_A6_SDM
DOUT_B1_SDM: J11.26 ; port DOUT_B1_SDM
DOUT_B2_SDM: J11.34 ; port DOUT_B2_SDM
DOUT_B3_SDM: J12.26 ; port DOUT_B3_SDM
DOUT_B4_SDM: J12.34 ; port DOUT_B4_SDM
DOUT_B5_SDM: J13.26 ; port DOUT_B5_SDM
DOUT_B6_SDM: J13.34 ; port DOUT_B6_SDM
DRV_FAULT5: U42.4(1A1) ; port DRV_FAULT5
DRV_FAULT6: U41.7(2A2) ; port DRV_FAULT6
DRV_FAULT_1: J11.17 R300.2 U46.4(A)
DRV_FAULT_2: J11.45 R299.2 U42.10(2B2)
DRV_FAULT_3: J12.17 R298.2 U42.11(2B1)
DRV_FAULT_4: J12.45 R297.2 U42.12(1B2)
DRV_FAULT_5: J13.17 R296.2 U42.13(1B1)
DRV_FAULT_6: J13.45 R292.2 U41.10(2B2)
DRV_OFF5: U43.5(1A2) ; port DRV_OFF5
DRV_OFF6: U43.4(1A1) ; port DRV_OFF6
DRV_OFF_1: J11.19 U45.10(2B2)
DRV_OFF_2: J11.47 U44.10(2B2)
DRV_OFF_3: J12.19 U43.10(2B2)
DRV_OFF_4: J12.47 U43.11(2B1)
DRV_OFF_5: J13.19 U43.12(1B2)
DRV_OFF_6: J13.47 U43.13(1B1)
DRV_SPI_CLK: TP37.1 U41.4(1A1) ; port DRV_SPI_CLK
DRV_SPI_CLK_3V3: J14.1 J14.3 J14.5 R293.2
DRV_SPI_CLK_AX12: J11.29 J14.2
DRV_SPI_CLK_AX34: J12.29 J14.4
DRV_SPI_CLK_AX56: J13.29 J14.6
DRV_SPI_CS0_AX12: U45.6(2A1) ; port DRV_SPI_CS0_AX12
DRV_SPI_CS1_AX34: U45.5(1A2) ; port DRV_SPI_CS1_AX34
DRV_SPI_CS2_AX56: U45.4(1A1) ; port DRV_SPI_CS2_AX56
DRV_SPI_CS_AX12: J11.43 R303.2
DRV_SPI_CS_AX34: J12.43 R302.2
DRV_SPI_CS_AX56: J13.43 R301.2
DRV_SPI_D0_3V3: J14.7 J14.9 J14.11 R294.2
DRV_SPI_D0_AX12: J11.27 J14.8
DRV_SPI_D0_AX34: J12.27 J14.10
DRV_SPI_D0_AX56: J13.27 J14.12
DRV_SPI_D1_3V3: J14.13 J14.15 J14.17 U41.11(2B1)
DRV_SPI_D1_AX12: J11.31 J14.14
DRV_SPI_D1_AX34: J12.31 J14.16
DRV_SPI_D1_AX56: J13.31 J14.18
DRV_SPI_MUX_S56: U44.4(1A1) ; port DRV_SPI_MUX_S56
DRV_SPI_MUX_S_12: J11.15 U44.11(2B1)
DRV_SPI_MUX_S_34: J12.15 U44.12(1B2)
DRV_SPI_MUX_S_56: J13.15 U44.13(1B1)
DRV_SPI_SDI: R295.1 TP39.1 ; port DRV_SPI_SDI
DRV_SPI_SDO: TP38.1 U41.5(1A2) ; port DRV_SPI_SDO
GPIO0_15: U44.6(2A1) ; port DRV_SPI_MUX_S12
GPIO0_16: U46.1(B) ; port DRV_FAULT1
GPIO0_17: U45.7(2A2) ; port DRV_OFF1
GPIO0_30: U42.7(2A2) ; port DRV_FAULT2
GPIO0_31: U44.7(2A2) ; port DRV_OFF2
GPIO0_32: U44.5(1A2) ; port DRV_SPI_MUX_S34
GPIO0_41: U42.6(2A1) ; port DRV_FAULT3
GPIO0_42: U43.7(2A2) ; port DRV_OFF3
GPIO0_43: U42.5(1A2) ; port DRV_FAULT4
GPIO0_44: U43.6(2A1) ; port DRV_OFF4
PWMA1H: J11.12 ; port PWMA1H
PWMA1L: J11.14 ; port PWMA1L
PWMA2H: J11.44 ; port PWMA2H
PWMA2L: J11.42 ; port PWMA2L
PWMA3H: J12.12 ; port PWMA3H
PWMA3L: J12.14 ; port PWMA3L
PWMA4H: J12.44 ; port PWMA4H
PWMA4L: J12.42 ; port PWMA4L
PWMA5H: J13.12 ; port PWMA5H
PWMA5L: J13.14 ; port PWMA5L
PWMA6H: J13.44 ; port PWMA6H
PWMA6L: J13.42 ; port PWMA6L
PWMB1H: J11.16 ; port PWMB1H
PWMB1L: J11.18 ; port PWMB1L
PWMB2H: J11.48 ; port PWMB2H
PWMB2L: J11.46 ; port PWMB2L
PWMB3H: J12.16 ; port PWMB3H
PWMB3L: J12.18 ; port PWMB3L
PWMB4H: J12.48 ; port PWMB4H
PWMB4L: J12.46 ; port PWMB4L
PWMB5H: J13.16 ; port PWMB5H
PWMB5L: J13.18 ; port PWMB5L
PWMB6H: J13.48 ; port PWMB6H
PWMB6L: J13.46 ; port PWMB6L
PWMC1H: J11.20 ; port PWMC1H
PWMC1L: J11.22 ; port PWMC1L
PWMC2H: J11.40 ; port PWMC2H
PWMC2L: J11.38 ; port PWMC2L
PWMC3H: J12.20 ; port PWMC3H
PWMC3L: J12.22 ; port PWMC3L
PWMC4H: J12.40 ; port PWMC4H
PWMC4L: J12.38 ; port PWMC4L
PWMC5H: J13.20 ; port PWMC5H
PWMC5L: J13.22 ; port PWMC5L
PWMC6H: J13.40 ; port PWMC6H
PWMC6L: J13.38 ; port PWMC6L
SDM_CLK_AX12: J11.23 ; port SDM_CLK_AX12
SDM_CLK_AX34: J12.23 ; port SDM_CLK_AX34
SDM_CLK_AX56: J13.23 ; port SDM_CLK_AX56
VSENSE_AX12: C177.2 D20.2(A) R311.1 R314.2 ; port VSENSE_AX12
VSENSE_AX34: C205.2 D21.2(A) R312.1 R315.2 ; port VSENSE_AX34
VSENSE_AX56: C206.2 D22.2(A) R313.1 R316.2 ; port VSENSE_AX56
NetC193_2: C193.2 R332.1 U41.1(VCCA) U41.2(1DIR)
NetC194_1: C194.1 R333.1 U41.16(VCCB)
NetC195_2: C195.2 R334.1 U42.1(VCCA)
NetC196_1: C196.1 R335.1 U42.16(VCCB)
NetC197_2: C197.2 R336.1 U43.1(VCCA) U43.2(1DIR) U43.3(2DIR)
NetC198_1: C198.1 R337.1 U43.16(VCCB)
NetC199_2: C199.2 R339.1 U44.1(VCCA) U44.2(1DIR) U44.3(2DIR)
NetC200_1: C200.1 R340.1 U44.16(VCCB)
NetC201_2: C201.2 R341.1 U45.1(VCCA) U45.2(1DIR) U45.3(2DIR)
NetC202_1: C202.1 R342.1 U45.16(VCCB)
NetC203_1: C203.1 R300.1 R338.1 U46.5(VCCA)
NetC204_1: C204.1 R343.1 U46.2(VCCB)
NetR293_1: R293.1 U41.13(1B1)
NetR294_1: R294.1 U41.12(1B2)
NetR295_2: R295.2 U41.6(2A1)
NetR301_1: R301.1 U45.13(1B1)
NetR302_1: R302.1 U45.12(1B2)
NetR303_1: R303.1 U45.11(2B1)

Not connected (* = marked no-connect by the designer): J11 35* 37* 39* 41*; J12 35* 37* 39* 41*; J13 35* 37* 39* 41*

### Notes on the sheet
- Connector to 3 BackPlane Daughter Board
- From J11 VBUS
- Silkscreen: DRV_SPI Signal select
  - Jumper Installed (1/3/5 - 2/4/6) - SPI CLK
  - Jumper Installed (7/9/11 - 8/10/12) - SPI D0
  - Jumper Installed (13/15/17 - 14/16/18) - SPI D1
- From J12 VBUS
- From J13 VBUS

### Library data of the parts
C177 C193-C202 C205 C206 = CMP-0006629-2: CAP, CERM, 0.1 uF, 10 V, +/- 10%, X7R, 0402; Manufacturer: MuRata; TaMin_C: -55°C; Polarized: N; SizeAreaWB_mm2: 3; Value1: Unknown; U/M: EA; Value: 0.1uF; TaMax_C: 125°C; SizeZ_mm: 0.6; SizeX_mm: 1; SizeY_mm: 0.5; Cap_F: 100nF; AEC Category: Q200
C203 C204 = CMP-0064970-1: CAP, CERM, 0.1 uF, 16 V,+/- 10%, X7R, 0201; Manufacturer: MuRata; TaMin_C: -55°C; Polarized: N; SizeAreaWB_mm2: 2.08; Value1: Unknown; U/M: EA; Value: 0.1uF; TaMax_C: 125°C; SizeZ_mm: 0.26; SizeX_mm: 0.6; SizeY_mm: 0.3; SizeArea_mm2: 0.18; Cap_F: 100nF; AEC Category: Q200
D20-D22 = CMP-0081199-2: Diode, Schottky, 30 V, 0.1 A, AEC-Q101, SOD-323; Manufacturer: Diodes Inc.; Value1: 0.1A; SizeArea_mm2: 3.645; Value: 30V; Vf_V: 1V; Io_A: 100mA; TJmax_C: 150°C; SizeY_mm: 1.35; SizeX_mm: 2.7; AEC Qualified: Y; SizeAreaWB_mm2: 8.695; SizeZ_mm: 1; AEC Category: Q101
J11-J13 = CMP-0055585-1: Header, 2.54mm, 25x2, Gold, TH; Manufacturer: Samtec; CNHeader: TRUE; Shrouded: N; Gender: Male; Cert_CSA: Y; Row_Count: 2; RowSpacing_mm: 2.54; CT: FALSE
J14 = CMP-0055593-1: Header, 2.54mm, 9x2, Gold, TH; Manufacturer: Samtec; CNHeader: TRUE; Current_A: 6.3A; Gender: Male; Cert_CSA: Y; Voltage_V: 550V; Row_Count: 2; RowSpacing_mm: 2.54; CT: FALSE
R292 R296-R300 = CMP-0025958-3: as R253 on sheet TIDA-010948-CB-Ethernet2
R293-R295 R301-R303 = CMP-0026880-3: as R247 on sheet TIDA-010948-CB-Ethernet2
R311-R313 = CMP-0025332-3: RES, 49.9 k, 0.5%, 0.1 W, 0603; Manufacturer: Yageo America; Power_W: 100mW; TempCo: 50 ppm/C; Value_Code: 49k9; U/M: EA; Value: 49.9k; EIA_Code: E192; SizeX_mm: 1.6; SizeY_mm: 0.8; SizeZ_mm: 1; Value2: 0.1W; SizeArea_mm2: 1.28; VDC_V: 75V; AEC Category: Q200
R314-R316 = CMP-0025223-3: RES, 3.40 k, 0.5%, 0.1 W, 0603; Manufacturer: Yageo America; Power_W: 100mW; Value_Code: 3k40; U/M: EA; Value: 3.40k; EIA_Code: E192; TempCo: 50 ppm/C; Res_ohm: 3.4k; SizeX_mm: 1.6; SizeY_mm: 0.8; SizeZ_mm: 1; Value2: 0.1W; SizeArea_mm2: 1.28; VDC_V: 75V; AEC Category: Q200
R332-R343 = CMP-0026992-3: RES, 0, 5%, 0.1 W, AEC-Q200 Grade 0, 0402; Manufacturer: Panasonic; Power_W: 100mW; TempCo: 600 ppm/C; Value_Code: 0000; Value: 0; EIA_Code: E24; SizeX_mm: 1; SizeY_mm: 0.5; SizeZ_mm: 0.6; Value2: 0.1W; AEC Qualified: Y; VDC_V: 50V; AEC Category: Q200; SizeAreaWB_mm2: 3
TP37-TP39 = CMP-0078143-3: TEST POINT.  No entry in BOM.
U41-U45 = CMP-0079319-1: Quad-Bit Bus Transceiver with Configurable Voltage Translation and 3-State Outputs, PW0016A (TSSOP-16); Alternate PartNumber: SN74AXC4T245PWR; Alternate Manufacturer: Texas Instruments; SizeAreaWB_mm2: 58.8; SizeZ_mm: 1.2; SizeX_mm: 6.4; SizeY_mm: 5; SizeArea_mm2: 32; CompType: IC; AEC Qualified: N; AEC Category: Q200
U46 = CMP-0078475-5: 1-Bit Dual-Supply Buffered Voltage Signal Converter, DCK0005A (SOT-SC70-5); Manufacturer: Texas Instruments; AEC Qualified: N; SizeArea_mm2: 4.2; CompType: IC; SizeAreaWB_mm2: 9.3; AEC Category: Q200; SizeY_mm: 2.0; SizeZ_mm: 1.1; SizeX_mm: 2.1

## Sheet TIDA-010948-CB-Hardware.SchDoc
size 431 x 279 mm; Date: Not shown in title block; ApprovedBy: Not shown in title block; CheckedBy: Not shown in title block; Author: Not shown in title block; CompanyName: Not shown in title block; Engineer: Not shown in title block; Organization: Not shown in title block; Address1: Not shown in title block; Address2: Not shown in title block; Address3: Not shown in title block; Address4: Not shown in title block; DocumentNumber: 11; Revision: Use project parameter SCH_Rev; SheetNumber: 11; SheetTotal: 11; PageSetup: Record=PageOptions¦CenterHorizontal=True¦CenterVertical=True¦PrintScale=1.00¦XCorrection=1.00¦YCorrection=1.00¦PrintKind=0¦BorderSize=5000000¦LeftOffset=0¦BottomOffset=0¦Orientation=2¦PaperLength=1000¦PaperWidth=1000¦Scale=100¦PaperSource=15¦PrintQuality=600¦MediaType=1¦DitherType=10¦PaperKind=Letter¦PrintScaleMode=1
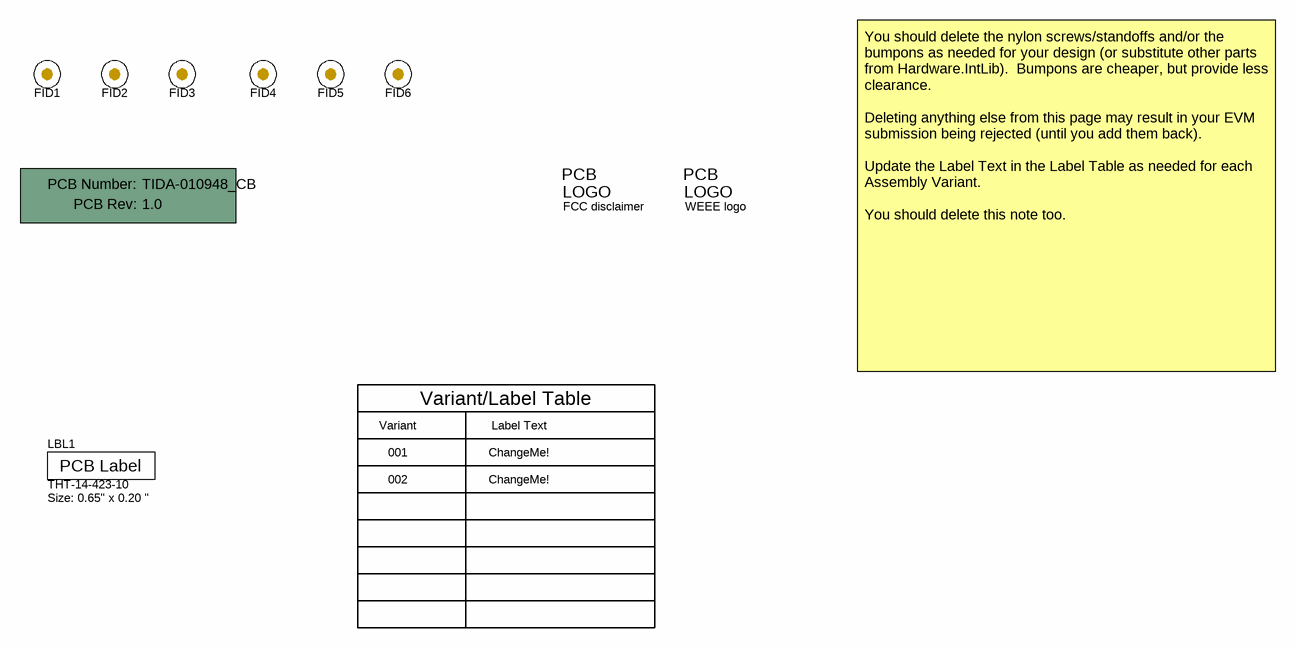
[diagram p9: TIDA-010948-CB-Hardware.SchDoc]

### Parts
!PCB1  Printed Circuit Board  (value not drawn)  (mechanical)
FID1  Fiducial  [Fiducial10-20]  (value not drawn)
FID2  Fiducial  [Fiducial10-20]  (value not drawn)
FID3  Fiducial  [Fiducial10-20]  (value not drawn)
FID4  Fiducial  [Fiducial10-20]  (value not drawn)
FID5  Fiducial  [Fiducial10-20]  (value not drawn)
FID6  Fiducial  [Fiducial10-20]  (value not drawn)
LBL1  THT-14-423-10  Note: Size: 0.65" x 0.20 "  [Label_650x200]
Logo2  FCC disclaimer  [FCC_disclaimer]  (no BOM)
Logo3  WEEE logo  [WEEE_Minimum]  (no BOM)

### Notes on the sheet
- Variant
- Variant/Label Table
- Label Text
- You should delete the nylon screws/standoffs and/or the bumpons as needed for your design (or substitute other parts from Hardware.IntLib).  Bumpons are cheaper, but provide less clearance.
  Deleting anything else from this page may result in your EVM submission being rejected (until you add them back).
  Update the Label Text in the Label Table as needed for each Assembly Variant.
  You should delete this note too.
- 001
- 002
- ChangeMe!

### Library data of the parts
!PCB1 = CMP-0003618-2: Manufacturer: Any; PartNumber: TIDA-010948_CB
FID1-FID6 = CMP-0077181-1: Fiducial mark.  There is nothing to buy or mount.
LBL1 = CMP-0003625-1: Thermal Transfer Printable Labels, 0.650" W x 0.200" H - 10,000 per roll; Manufacturer: Brady; CompType: Label
Logo2 = CMP-0074847-1: FCC_disclaimer; Library Reference: Logo
Logo3 = CMP-0074769-1

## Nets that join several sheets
1V1: TIDA-010948-CB-Power (7 pins), TIDA-010948-CB-Ethernet1 (L8.2), TIDA-010948-CB-Ethernet2 (L11.2)
1V8: TIDA-010948-CB-Power (9 pins), TIDA-010948-CB-SDFM (R241.2 R276.2 R291.2), TIDA-010948-CB-PRUIO_CLKGEN (L3.2 L5.2 R236.2 R319.2), TIDA-010948-CB-PWM (12 pins), TIDA-010948-CB-Ethernet1 (L6.2), TIDA-010948-CB-Ethernet2 (L9.2), TIDA-010948-CB-Interface (9 pins)
2V5: TIDA-010948-CB-Power (7 pins), TIDA-010948-CB-Ethernet1 (L7.2), TIDA-010948-CB-Ethernet2 (L10.2)
3V3: TIDA-010948-CB-Power (16 pins), TIDA-010948-CB-SDFM (R268.2 R281.2 R317.2), TIDA-010948-CB-PRUIO_CLKGEN (6 pins), TIDA-010948-CB-PWM (6 pins), TIDA-010948-CB-Ethernet1 (R240.2 R244.1), TIDA-010948-CB-Ethernet2 (R280.2 R284.1), TIDA-010948-CB-Interface (17 pins)
5V: TIDA-010948-CB-Power (16 pins), TIDA-010948-CB-Interface (J11.8 J12.8 J13.8)
EARTH_GND: TIDA-010948-CB-Ethernet1 (10 pins), TIDA-010948-CB-Ethernet2 (C183.2 J9.13 J9.14 R288.1)
GND: TIDA-010948-CB-Power (178 pins), TIDA-010948-CB-Bootmode (33 pins), TIDA-010948-CB-Debug (24 pins), TIDA-010948-CB-SDFM (24 pins), TIDA-010948-CB-PRUIO_CLKGEN (24 pins), TIDA-010948-CB-PWM (120 pins), TIDA-010948-CB-Ethernet1 (56 pins), TIDA-010948-CB-Ethernet2 (54 pins), TIDA-010948-CB-Interface (81 pins)
V_1V8_MOD: TIDA-010948-CB-Power (MD1.K21), TIDA-010948-CB-Bootmode (26 pins), TIDA-010948-CB-Debug (7 pins)
V_VDDSHV5_SD: TIDA-010948-CB-Power (MD1.Y19), TIDA-010948-CB-Debug (C46.1 U17.A2 U17.B2)
VBUS: TIDA-010948-CB-Power (12 pins), TIDA-010948-CB-Interface (15 pins)
CLKOUT0: TIDA-010948-CB-Debug (R304.1 TP21.1), TIDA-010948-CB-Ethernet1 (R305.1)
DOUT_A1: TIDA-010948-CB-SDFM (R95.1), TIDA-010948-CB-PRUIO_CLKGEN (MD1.F5)
DOUT_A1_SDM: TIDA-010948-CB-SDFM (U18.13), TIDA-010948-CB-Interface (J11.28)
DOUT_A2: TIDA-010948-CB-SDFM (R97.1), TIDA-010948-CB-PRUIO_CLKGEN (MD1.H1)
DOUT_A2_SDM: TIDA-010948-CB-SDFM (U18.11), TIDA-010948-CB-Interface (J11.32)
DOUT_A3: TIDA-010948-CB-SDFM (R99.1), TIDA-010948-CB-PRUIO_CLKGEN (MD1.J2)
DOUT_A3_SDM: TIDA-010948-CB-SDFM (U19.13), TIDA-010948-CB-Interface (J12.28)
DOUT_A4: TIDA-010948-CB-SDFM (R101.1), TIDA-010948-CB-PRUIO_CLKGEN (MD1.M4)
DOUT_A4_SDM: TIDA-010948-CB-SDFM (U19.11), TIDA-010948-CB-Interface (J12.32)
DOUT_A5: TIDA-010948-CB-SDFM (R103.1), TIDA-010948-CB-PRUIO_CLKGEN (MD1.N5)
DOUT_A5_SDM: TIDA-010948-CB-SDFM (U20.13), TIDA-010948-CB-Interface (J13.28)
DOUT_A6: TIDA-010948-CB-SDFM (R105.1), TIDA-010948-CB-PRUIO_CLKGEN (MD1.P5)
DOUT_A6_SDM: TIDA-010948-CB-SDFM (U20.11), TIDA-010948-CB-Interface (J13.32)
DOUT_B1: TIDA-010948-CB-SDFM (R96.1), TIDA-010948-CB-PRUIO_CLKGEN (MD1.G3)
DOUT_B1_SDM: TIDA-010948-CB-SDFM (U18.12), TIDA-010948-CB-Interface (J11.26)
DOUT_B2: TIDA-010948-CB-SDFM (R98.1), TIDA-010948-CB-PRUIO_CLKGEN (MD1.H4)
DOUT_B2_SDM: TIDA-010948-CB-SDFM (U18.10), TIDA-010948-CB-Interface (J11.34)
DOUT_B3: TIDA-010948-CB-SDFM (R100.1), TIDA-010948-CB-PRUIO_CLKGEN (MD1.J5)
DOUT_B3_SDM: TIDA-010948-CB-SDFM (U19.12), TIDA-010948-CB-Interface (J12.26)
DOUT_B4: TIDA-010948-CB-SDFM (R102.1), TIDA-010948-CB-PRUIO_CLKGEN (MD1.N2)
DOUT_B4_SDM: TIDA-010948-CB-SDFM (U19.10), TIDA-010948-CB-Interface (J12.34)
DOUT_B5: TIDA-010948-CB-SDFM (R104.1), TIDA-010948-CB-PRUIO_CLKGEN (MD1.P2)
DOUT_B5_SDM: TIDA-010948-CB-SDFM (U20.12), TIDA-010948-CB-Interface (J13.26)
DOUT_B6: TIDA-010948-CB-SDFM (R106.1), TIDA-010948-CB-PRUIO_CLKGEN (MD1.R3)
DOUT_B6_SDM: TIDA-010948-CB-SDFM (U20.10), TIDA-010948-CB-Interface (J13.34)
DRV_FAULT5: TIDA-010948-CB-Debug (MD1.B16), TIDA-010948-CB-Interface (U42.4)
DRV_FAULT6: TIDA-010948-CB-Debug (MD1.D15), TIDA-010948-CB-Interface (U41.7)
DRV_OFF5: TIDA-010948-CB-Debug (MD1.C16), TIDA-010948-CB-Interface (U43.5)
DRV_OFF6: TIDA-010948-CB-Debug (MD1.E16), TIDA-010948-CB-Interface (U43.4)
DRV_SPI_CLK: TIDA-010948-CB-Debug (R65.1), TIDA-010948-CB-Interface (TP37.1 U41.4)
DRV_SPI_CS0_AX12: TIDA-010948-CB-Debug (MD1.U21), TIDA-010948-CB-Interface (U45.6)
DRV_SPI_CS1_AX34: TIDA-010948-CB-Debug (MD1.U19), TIDA-010948-CB-Interface (U45.5)
DRV_SPI_CS2_AX56: TIDA-010948-CB-Debug (MD1.D17), TIDA-010948-CB-Interface (U45.4)
DRV_SPI_MUX_S56: TIDA-010948-CB-Debug (MD1.E17), TIDA-010948-CB-Interface (U44.4)
DRV_SPI_SDI: TIDA-010948-CB-Debug (MD1.T20), TIDA-010948-CB-Interface (R295.1 TP39.1)
DRV_SPI_SDO: TIDA-010948-CB-Debug (R66.1), TIDA-010948-CB-Interface (TP38.1 U41.5)
ETH1_LED_0: TIDA-010948-CB-PRUIO_CLKGEN (MD1.B12), TIDA-010948-CB-Ethernet1 (5 pins)
ETH1_RGMII1_RD0: TIDA-010948-CB-PRUIO_CLKGEN (MD1.A14), TIDA-010948-CB-Ethernet1 (R213.1 R221.2 R233.1)
ETH1_RGMII1_RD1: TIDA-010948-CB-PRUIO_CLKGEN (MD1.B14), TIDA-010948-CB-Ethernet1 (R214.1 R222.2 R234.1)
ETH1_RGMII1_RD2: TIDA-010948-CB-PRUIO_CLKGEN (MD1.D14), TIDA-010948-CB-Ethernet1 (R237.1)
ETH1_RGMII1_RD3: TIDA-010948-CB-PRUIO_CLKGEN (MD1.E14), TIDA-010948-CB-Ethernet1 (R238.1)
ETH1_RGMII1_RX_CTL: TIDA-010948-CB-PRUIO_CLKGEN (MD1.B13), TIDA-010948-CB-Ethernet1 (R215.1 R223.2 TP33.1 U31.38)
ETH1_RGMII1_RX_ER: TIDA-010948-CB-PRUIO_CLKGEN (MD1.C13), TIDA-010948-CB-Ethernet1 (R228.2)
ETH1_RGMII1_RXC: TIDA-010948-CB-PRUIO_CLKGEN (MD1.E13), TIDA-010948-CB-Ethernet1 (R230.1 TP12.1)
ETH1_RGMII1_TD0: TIDA-010948-CB-PRUIO_CLKGEN (R113.1), TIDA-010948-CB-Ethernet1 (U31.28)
ETH1_RGMII1_TD1: TIDA-010948-CB-PRUIO_CLKGEN (R114.1), TIDA-010948-CB-Ethernet1 (U31.27)
ETH1_RGMII1_TD2: TIDA-010948-CB-PRUIO_CLKGEN (R115.1), TIDA-010948-CB-Ethernet1 (U31.26)
ETH1_RGMII1_TD3: TIDA-010948-CB-PRUIO_CLKGEN (R116.1), TIDA-010948-CB-Ethernet1 (U31.25)
ETH1_RGMII1_TX_CTL: TIDA-010948-CB-PRUIO_CLKGEN (MD1.C10), TIDA-010948-CB-Ethernet1 (TP11.1 U31.37)
ETH1_RGMII1_TXC: TIDA-010948-CB-PRUIO_CLKGEN (R117.1), TIDA-010948-CB-Ethernet1 (TP10.1 U31.29)
ETH2_LED_0: TIDA-010948-CB-PRUIO_CLKGEN (MD1.B6), TIDA-010948-CB-Ethernet2 (5 pins)
ETH2_RGMII2_RD0: TIDA-010948-CB-PRUIO_CLKGEN (MD1.E9), TIDA-010948-CB-Ethernet2 (R253.1 R261.2 R273.1)
ETH2_RGMII2_RD1: TIDA-010948-CB-PRUIO_CLKGEN (MD1.A8), TIDA-010948-CB-Ethernet2 (R254.1 R262.2 R274.1)
ETH2_RGMII2_RD2: TIDA-010948-CB-PRUIO_CLKGEN (MD1.C8), TIDA-010948-CB-Ethernet2 (R277.1)
ETH2_RGMII2_RD3: TIDA-010948-CB-PRUIO_CLKGEN (MD1.D8), TIDA-010948-CB-Ethernet2 (R278.1)
ETH2_RGMII2_RX_CTL: TIDA-010948-CB-PRUIO_CLKGEN (MD1.B7), TIDA-010948-CB-Ethernet2 (R255.1 R263.2 TP17.1 U36.38)
ETH2_RGMII2_RX_ER: TIDA-010948-CB-PRUIO_CLKGEN (MD1.C7), TIDA-010948-CB-Ethernet2 (R247.2)
ETH2_RGMII2_RXC: TIDA-010948-CB-PRUIO_CLKGEN (MD1.E7), TIDA-010948-CB-Ethernet2 (R270.1 TP18.1)
ETH2_RGMII2_TD0: TIDA-010948-CB-PRUIO_CLKGEN (R122.1), TIDA-010948-CB-Ethernet2 (U36.28)
ETH2_RGMII2_TD1: TIDA-010948-CB-PRUIO_CLKGEN (R123.1), TIDA-010948-CB-Ethernet2 (U36.27)
ETH2_RGMII2_TD2: TIDA-010948-CB-PRUIO_CLKGEN (R124.1), TIDA-010948-CB-Ethernet2 (U36.26)
ETH2_RGMII2_TD3: TIDA-010948-CB-PRUIO_CLKGEN (R125.1), TIDA-010948-CB-Ethernet2 (U36.25)
ETH2_RGMII2_TX_CTL: TIDA-010948-CB-PRUIO_CLKGEN (MD1.C4), TIDA-010948-CB-Ethernet2 (TP16.1 U36.37)
ETH2_RGMII2_TXC: TIDA-010948-CB-PRUIO_CLKGEN (R126.1), TIDA-010948-CB-Ethernet2 (TP15.1 U36.29)
GPIO0_15: TIDA-010948-CB-Bootmode (U7.1), TIDA-010948-CB-Interface (U44.6)
GPIO0_16: TIDA-010948-CB-Bootmode (U7.4), TIDA-010948-CB-Interface (U46.1)
GPIO0_17: TIDA-010948-CB-Bootmode (U7.8), TIDA-010948-CB-Interface (U45.7)
GPIO0_30: TIDA-010948-CB-Bootmode (U10.11), TIDA-010948-CB-Interface (U42.7)
GPIO0_31: TIDA-010948-CB-Bootmode (MD1.AB11), TIDA-010948-CB-Interface (U44.7)
GPIO0_32: TIDA-010948-CB-Bootmode (MD1.Y11), TIDA-010948-CB-Interface (U44.5)
GPIO0_41: TIDA-010948-CB-Bootmode (MD1.AB12), TIDA-010948-CB-Interface (U42.6)
GPIO0_42: TIDA-010948-CB-Bootmode (MD1.AA12), TIDA-010948-CB-Interface (U43.7)
GPIO0_43: TIDA-010948-CB-Bootmode (MD1.W12), TIDA-010948-CB-Interface (U42.5)
GPIO0_44: TIDA-010948-CB-Bootmode (MD1.W11), TIDA-010948-CB-Interface (U43.6)
PHY1_CLK_IN: TIDA-010948-CB-PRUIO_CLKGEN (R107.2), TIDA-010948-CB-Ethernet1 (R246.1)
PHY1_RESET: TIDA-010948-CB-Debug (MD1.L20), TIDA-010948-CB-Ethernet1 (R243.2 TP32.1 U31.43)
PHY2_CLK_IN: TIDA-010948-CB-PRUIO_CLKGEN (R108.2), TIDA-010948-CB-Ethernet2 (R286.1)
PHY2_RESET: TIDA-010948-CB-Debug (MD1.Y16), TIDA-010948-CB-Ethernet2 (R283.2 TP36.1 U36.43)
PHY_INT: TIDA-010948-CB-Debug (MD1.K20), TIDA-010948-CB-Ethernet1 (R242.2 U31.44), TIDA-010948-CB-Ethernet2 (R282.2 U36.44)
PHY_MDC: TIDA-010948-CB-PRUIO_CLKGEN (MD1.A15), TIDA-010948-CB-Ethernet1 (U31.42), TIDA-010948-CB-Ethernet2 (U36.42)
PHY_MDIO: TIDA-010948-CB-PRUIO_CLKGEN (MD1.C15 R236.1), TIDA-010948-CB-Ethernet1 (U31.41), TIDA-010948-CB-Ethernet2 (U36.41)
PORz_OUT: TIDA-010948-CB-Bootmode (R59.1 TP20.1), TIDA-010948-CB-Debug (D10.2 MD1.F7)
PWM_A1_H: TIDA-010948-CB-Debug (MD1.W21), TIDA-010948-CB-PWM (R145.1 U25.3)
PWM_A1_L: TIDA-010948-CB-Debug (MD1.V19), TIDA-010948-CB-PWM (R146.1 U25.4)
PWM_A2_H: TIDA-010948-CB-Bootmode (MD1.V9), TIDA-010948-CB-PWM (R173.1 U27.3)
PWM_A2_L: TIDA-010948-CB-Bootmode (MD1.U5), TIDA-010948-CB-PWM (R174.1 U27.4)
PWM_A3_H: TIDA-010948-CB-Bootmode (U9.1), TIDA-010948-CB-PWM (R151.1 U26.3)
PWM_A3_L: TIDA-010948-CB-Bootmode (U9.4), TIDA-010948-CB-PWM (R152.1 U26.4)
PWM_A4_H: TIDA-010948-CB-Bootmode (MD1.U7), TIDA-010948-CB-PWM (R179.1 U28.3)
PWM_A4_L: TIDA-010948-CB-Bootmode (MD1.U8), TIDA-010948-CB-PWM (R180.1 U28.4)
PWM_A5_H: TIDA-010948-CB-PRUIO_CLKGEN (MD1.R4), TIDA-010948-CB-PWM (R193.1 U29.3)
PWM_A5_L: TIDA-010948-CB-PRUIO_CLKGEN (MD1.T2), TIDA-010948-CB-PWM (R194.1 U29.4)
PWM_A6_H: TIDA-010948-CB-PRUIO_CLKGEN (MD1.K2), TIDA-010948-CB-PWM (R207.1 U30.3)
PWM_A6_L: TIDA-010948-CB-PRUIO_CLKGEN (MD1.K3), TIDA-010948-CB-PWM (R208.1 U30.4)
PWM_B1_H: TIDA-010948-CB-PRUIO_CLKGEN (MD1.B9), TIDA-010948-CB-PWM (R147.1 U25.5)
PWM_B1_L: TIDA-010948-CB-PRUIO_CLKGEN (MD1.D9), TIDA-010948-CB-PWM (R148.1 U25.6)
PWM_B2_H: TIDA-010948-CB-Bootmode (MD1.V7), TIDA-010948-CB-PWM (R175.1 U27.5)
PWM_B2_L: TIDA-010948-CB-Bootmode (MD1.V6), TIDA-010948-CB-PWM (R176.1 U27.6)
PWM_B3_H: TIDA-010948-CB-Bootmode (U8.4), TIDA-010948-CB-PWM (R153.1 U26.5)
PWM_B3_L: TIDA-010948-CB-Bootmode (U8.8), TIDA-010948-CB-PWM (R154.1 U26.6)
PWM_B4_H: TIDA-010948-CB-Bootmode (MD1.V10), TIDA-010948-CB-PWM (R181.1 U28.5)
PWM_B4_L: TIDA-010948-CB-Bootmode (MD1.V4), TIDA-010948-CB-PWM (R182.1 U28.6)
PWM_B5_H: TIDA-010948-CB-PRUIO_CLKGEN (MD1.T3), TIDA-010948-CB-PWM (R195.1 U29.5)
PWM_B5_L: TIDA-010948-CB-PRUIO_CLKGEN (MD1.T5), TIDA-010948-CB-PWM (R196.1 U29.6)
PWM_B6_H: TIDA-010948-CB-PRUIO_CLKGEN (MD1.K5), TIDA-010948-CB-PWM (R209.1 U30.5)
PWM_B6_L: TIDA-010948-CB-PRUIO_CLKGEN (MD1.L1), TIDA-010948-CB-PWM (R210.1 U30.6)
PWM_C1_H: TIDA-010948-CB-Bootmode (U9.11), TIDA-010948-CB-PWM (R149.1 U25.7)
PWM_C1_L: TIDA-010948-CB-Bootmode (U10.1), TIDA-010948-CB-PWM (R150.1 U25.8)
PWM_C2_H: TIDA-010948-CB-Bootmode (U10.4), TIDA-010948-CB-PWM (R177.1 U27.7)
PWM_C2_L: TIDA-010948-CB-Bootmode (U10.8), TIDA-010948-CB-PWM (R178.1 U27.8)
PWM_C3_H: TIDA-010948-CB-Bootmode (U7.11), TIDA-010948-CB-PWM (R155.1 U26.7)
PWM_C3_L: TIDA-010948-CB-Bootmode (U8.1), TIDA-010948-CB-PWM (R156.1 U26.8)
PWM_C4_H: TIDA-010948-CB-Bootmode (U8.11), TIDA-010948-CB-PWM (R183.1 U28.7)
PWM_C4_L: TIDA-010948-CB-Bootmode (U9.8), TIDA-010948-CB-PWM (R184.1 U28.8)
PWM_C5_H: TIDA-010948-CB-PRUIO_CLKGEN (MD1.U1), TIDA-010948-CB-PWM (R197.1 U29.7)
PWM_C5_L: TIDA-010948-CB-PRUIO_CLKGEN (MD1.U2), TIDA-010948-CB-PWM (R198.1 U29.8)
PWM_C6_H: TIDA-010948-CB-PRUIO_CLKGEN (MD1.L3), TIDA-010948-CB-PWM (R211.1 U30.7)
PWM_C6_L: TIDA-010948-CB-PRUIO_CLKGEN (MD1.L4), TIDA-010948-CB-PWM (R212.1 U30.8)
PWMA1H: TIDA-010948-CB-PWM (C72.1 R133.2), TIDA-010948-CB-Interface (J11.12)
PWMA1L: TIDA-010948-CB-PWM (C71.1 R135.2), TIDA-010948-CB-Interface (J11.14)
PWMA2H: TIDA-010948-CB-PWM (C86.1 R161.2), TIDA-010948-CB-Interface (J11.44)
PWMA2L: TIDA-010948-CB-PWM (C85.1 R163.2), TIDA-010948-CB-Interface (J11.42)
PWMA3H: TIDA-010948-CB-PWM (C78.1 R134.2), TIDA-010948-CB-Interface (J12.12)
PWMA3L: TIDA-010948-CB-PWM (C77.1 R136.2), TIDA-010948-CB-Interface (J12.14)
PWMA4H: TIDA-010948-CB-PWM (C92.1 R162.2), TIDA-010948-CB-Interface (J12.44)
PWMA4L: TIDA-010948-CB-PWM (C91.1 R164.2), TIDA-010948-CB-Interface (J12.42)
PWMA5H: TIDA-010948-CB-PWM (C100.1 R187.2), TIDA-010948-CB-Interface (J13.12)
PWMA5L: TIDA-010948-CB-PWM (C99.1 R188.2), TIDA-010948-CB-Interface (J13.14)
PWMA6H: TIDA-010948-CB-PWM (C107.1 R201.2), TIDA-010948-CB-Interface (J13.44)
PWMA6L: TIDA-010948-CB-PWM (C106.1 R202.2), TIDA-010948-CB-Interface (J13.42)
PWMB1H: TIDA-010948-CB-PWM (C70.1 R137.2), TIDA-010948-CB-Interface (J11.16)
PWMB1L: TIDA-010948-CB-PWM (C69.1 R139.2), TIDA-010948-CB-Interface (J11.18)
PWMB2H: TIDA-010948-CB-PWM (C84.1 R165.2), TIDA-010948-CB-Interface (J11.48)
PWMB2L: TIDA-010948-CB-PWM (C83.1 R167.2), TIDA-010948-CB-Interface (J11.46)
PWMB3H: TIDA-010948-CB-PWM (C76.1 R138.2), TIDA-010948-CB-Interface (J12.16)
PWMB3L: TIDA-010948-CB-PWM (C75.1 R140.2), TIDA-010948-CB-Interface (J12.18)
PWMB4H: TIDA-010948-CB-PWM (C90.1 R166.2), TIDA-010948-CB-Interface (J12.48)
PWMB4L: TIDA-010948-CB-PWM (C89.1 R168.2), TIDA-010948-CB-Interface (J12.46)
PWMB5H: TIDA-010948-CB-PWM (C98.1 R189.2), TIDA-010948-CB-Interface (J13.16)
PWMB5L: TIDA-010948-CB-PWM (C97.1 R190.2), TIDA-010948-CB-Interface (J13.18)
PWMB6H: TIDA-010948-CB-PWM (C105.1 R203.2), TIDA-010948-CB-Interface (J13.48)
PWMB6L: TIDA-010948-CB-PWM (C104.1 R204.2), TIDA-010948-CB-Interface (J13.46)
PWMC1H: TIDA-010948-CB-PWM (C68.1 R141.2), TIDA-010948-CB-Interface (J11.20)
PWMC1L: TIDA-010948-CB-PWM (C67.1 R143.2), TIDA-010948-CB-Interface (J11.22)
PWMC2H: TIDA-010948-CB-PWM (C82.1 R169.2), TIDA-010948-CB-Interface (J11.40)
PWMC2L: TIDA-010948-CB-PWM (C81.1 R171.2), TIDA-010948-CB-Interface (J11.38)
PWMC3H: TIDA-010948-CB-PWM (C74.1 R142.2), TIDA-010948-CB-Interface (J12.20)
PWMC3L: TIDA-010948-CB-PWM (C73.1 R144.2), TIDA-010948-CB-Interface (J12.22)
PWMC4H: TIDA-010948-CB-PWM (C88.1 R170.2), TIDA-010948-CB-Interface (J12.40)
PWMC4L: TIDA-010948-CB-PWM (C87.1 R172.2), TIDA-010948-CB-Interface (J12.38)
PWMC5H: TIDA-010948-CB-PWM (C96.1 R191.2), TIDA-010948-CB-Interface (J13.20)
PWMC5L: TIDA-010948-CB-PWM (C95.1 R192.2), TIDA-010948-CB-Interface (J13.22)
PWMC6H: TIDA-010948-CB-PWM (C103.1 R205.2), TIDA-010948-CB-Interface (J13.40)
PWMC6L: TIDA-010948-CB-PWM (C102.1 R206.2), TIDA-010948-CB-Interface (J13.38)
SDM_CLK_AX12: TIDA-010948-CB-PRUIO_CLKGEN (R111.2), TIDA-010948-CB-Interface (J11.23)
SDM_CLK_AX34: TIDA-010948-CB-PRUIO_CLKGEN (R112.2), TIDA-010948-CB-Interface (J12.23)
SDM_CLK_AX56: TIDA-010948-CB-PRUIO_CLKGEN (R110.2), TIDA-010948-CB-Interface (J13.23)
SYSCLKOUT0: TIDA-010948-CB-Debug (R220.1 TP13.1), TIDA-010948-CB-Ethernet2 (R260.1)
TQMaX4XxL_PGOOD: TIDA-010948-CB-Power (R19.2 U3.1), TIDA-010948-CB-Debug (MD1.N6 TP22.1)
VSENSE_AX12: TIDA-010948-CB-Debug (R73.1), TIDA-010948-CB-Interface (C177.2 D20.2 R311.1 R314.2)
VSENSE_AX34: TIDA-010948-CB-Debug (R75.1), TIDA-010948-CB-Interface (C205.2 D21.2 R312.1 R315.2)
VSENSE_AX56: TIDA-010948-CB-Debug (R77.1), TIDA-010948-CB-Interface (C206.2 D22.2 R313.1 R316.2)

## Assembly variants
Variant of TIDA-010948-CB: not fitted J8 Logo1 R109 R213 R214 R216 R217 R218 R219 R221 R222 R223 R254 R256 R257 R258 R259 R260 R262 R263 R305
